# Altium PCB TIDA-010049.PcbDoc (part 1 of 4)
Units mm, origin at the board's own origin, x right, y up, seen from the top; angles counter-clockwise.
Board outline 75 x 60 mm, 4 copper layers (Top Layer, GND, Supply, Bottom Layer), stack 1.565 mm thick; 309 components, 186 nets, 995 pads, 362 vias.
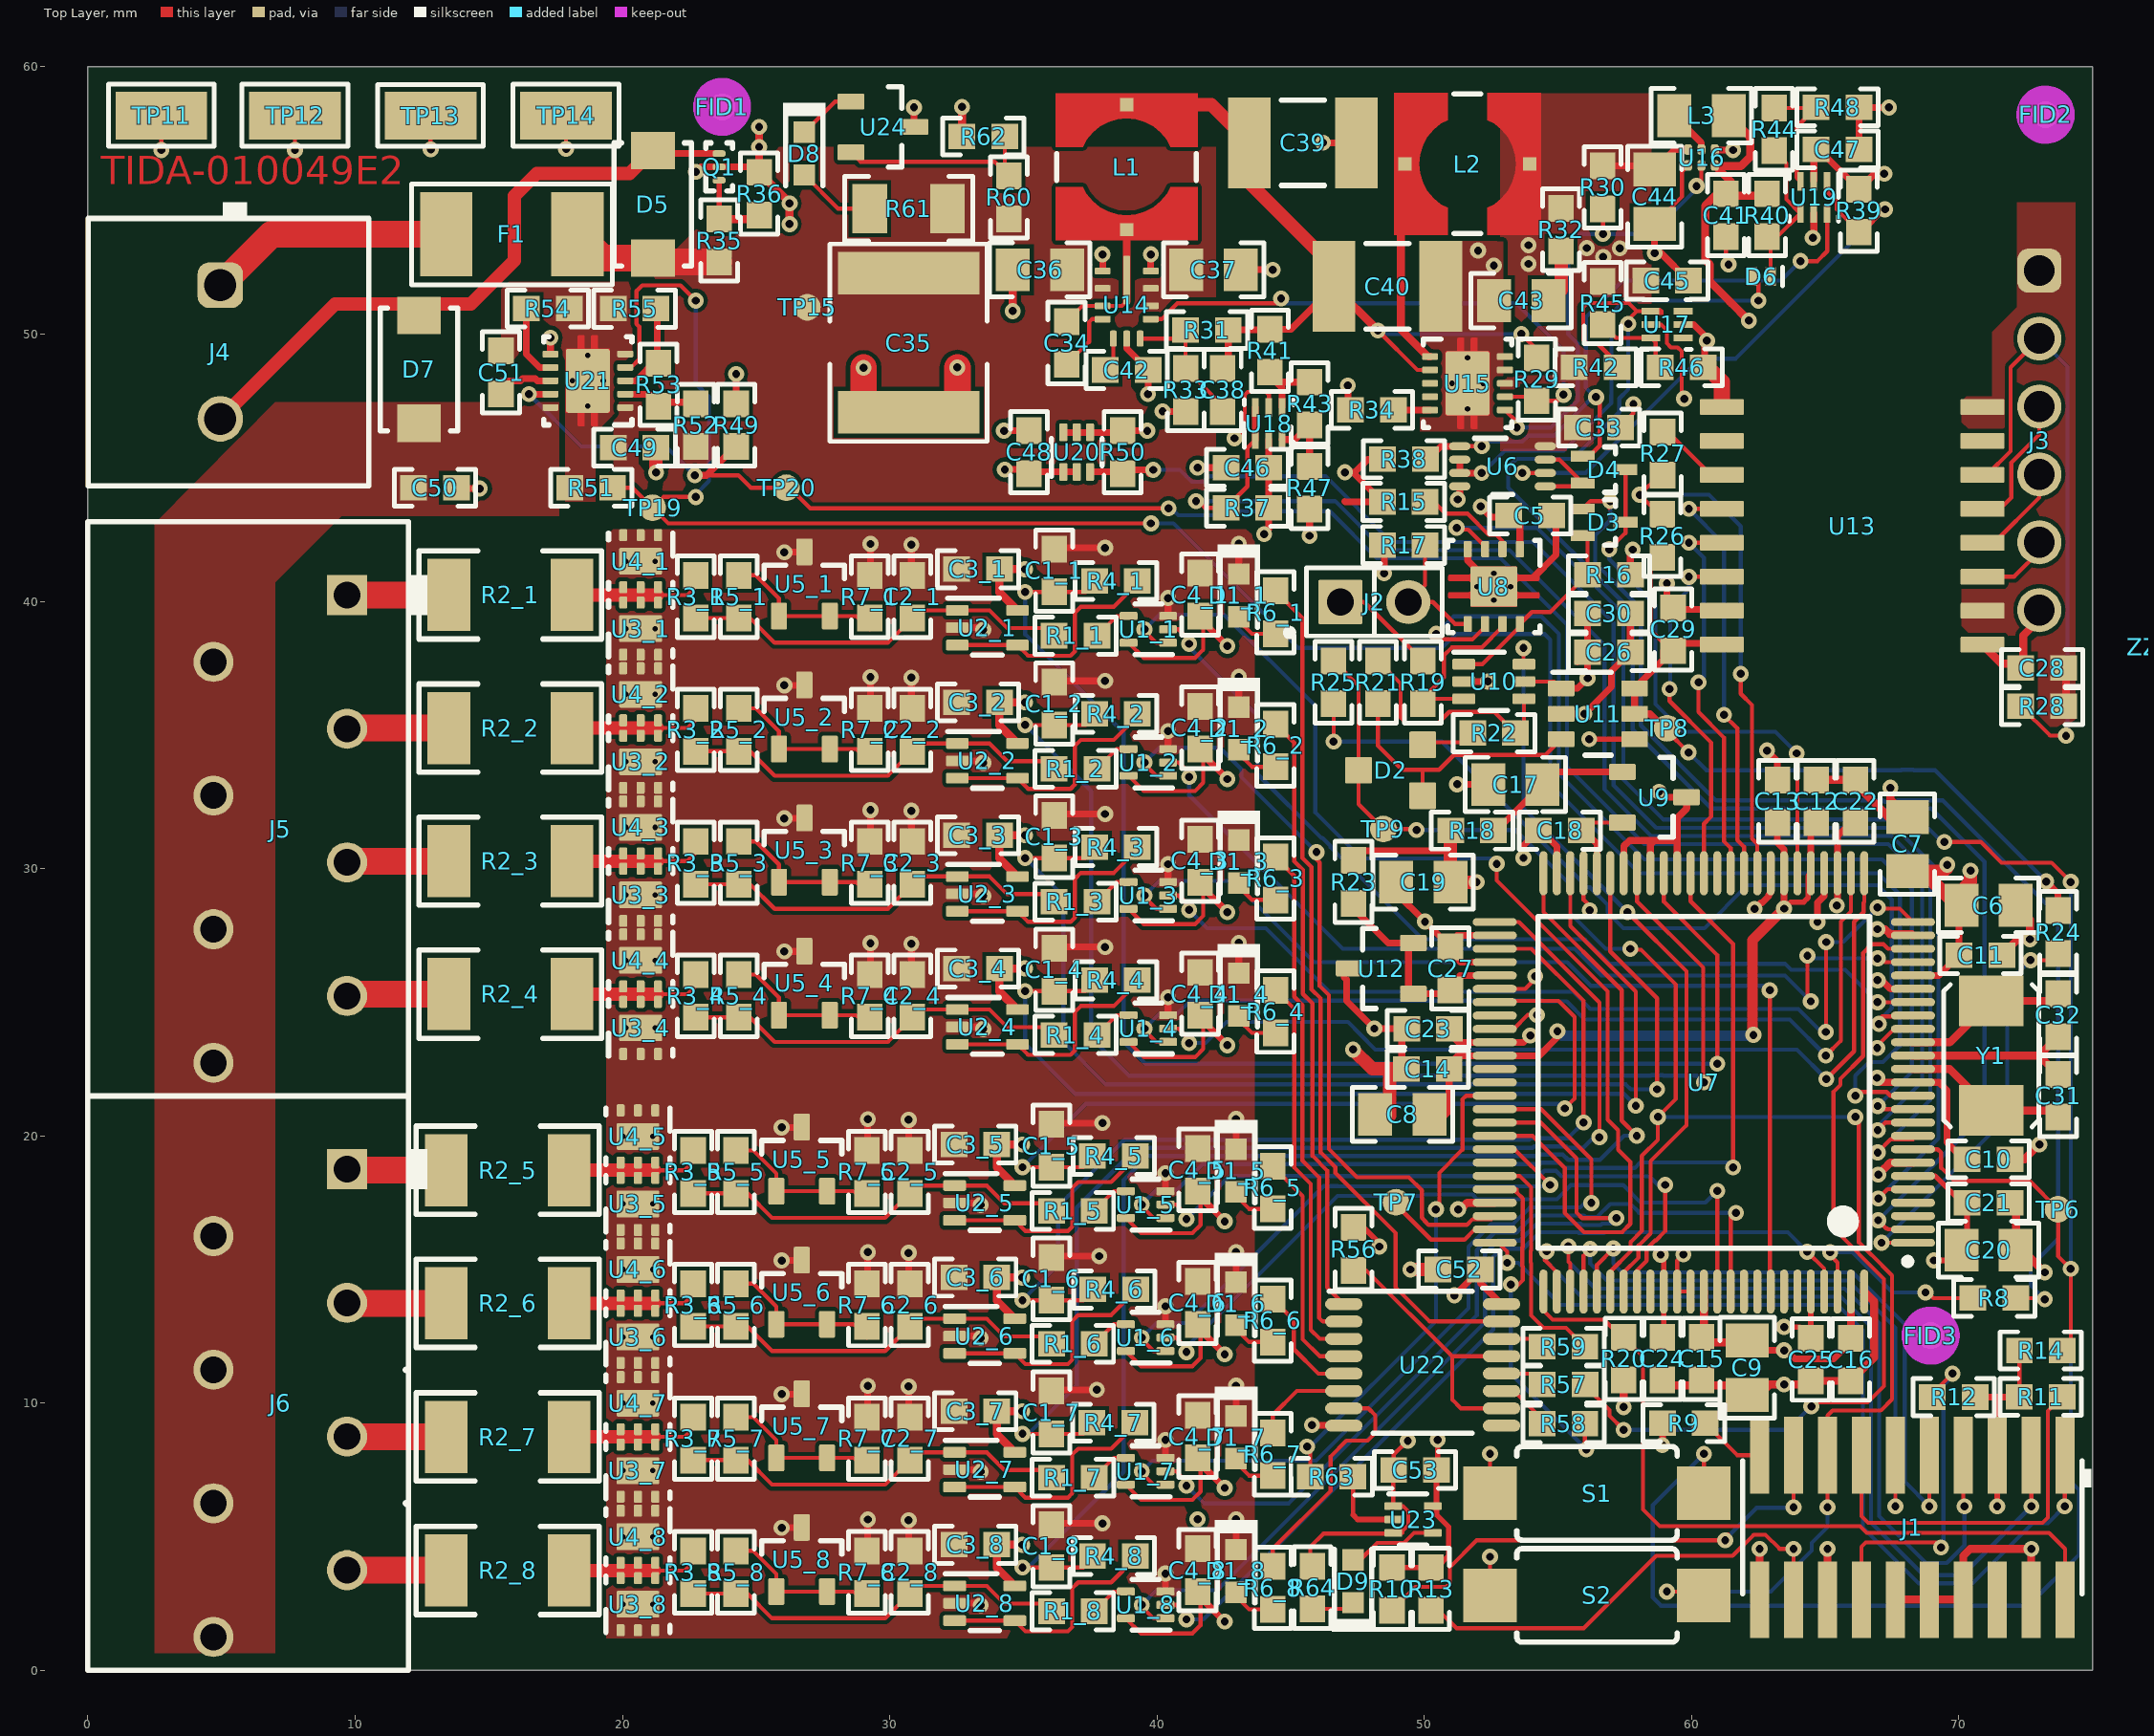
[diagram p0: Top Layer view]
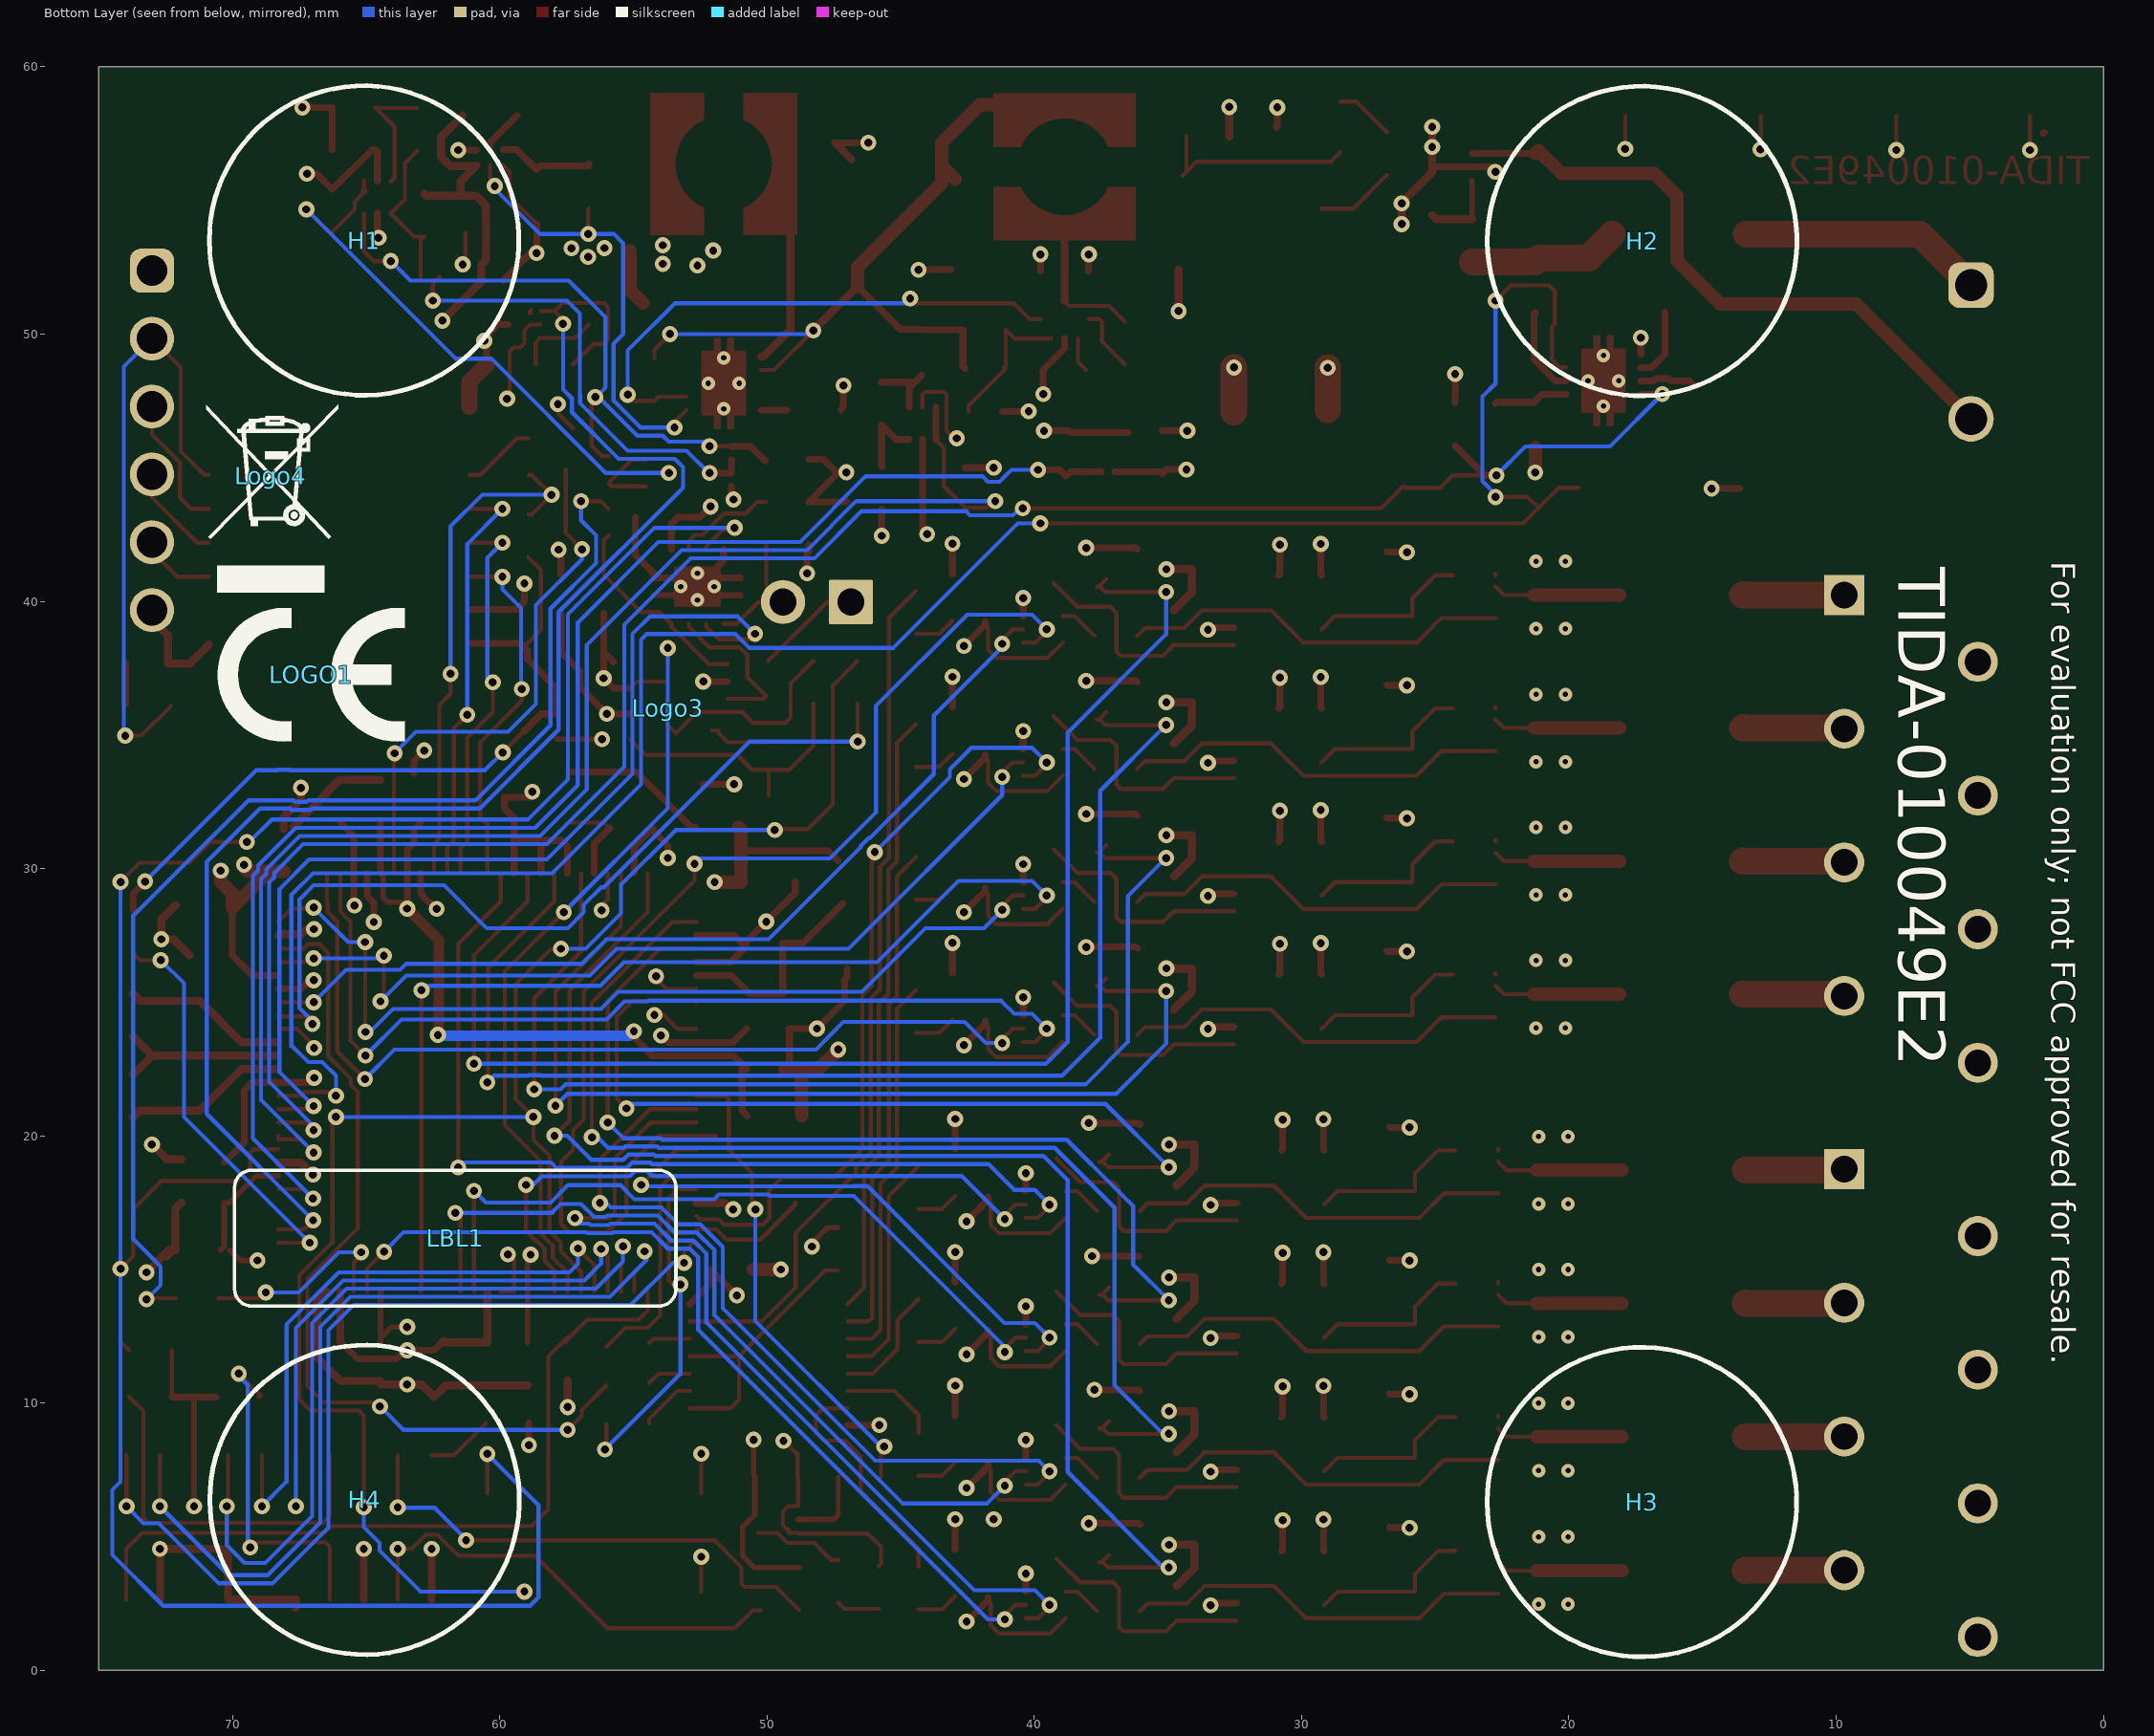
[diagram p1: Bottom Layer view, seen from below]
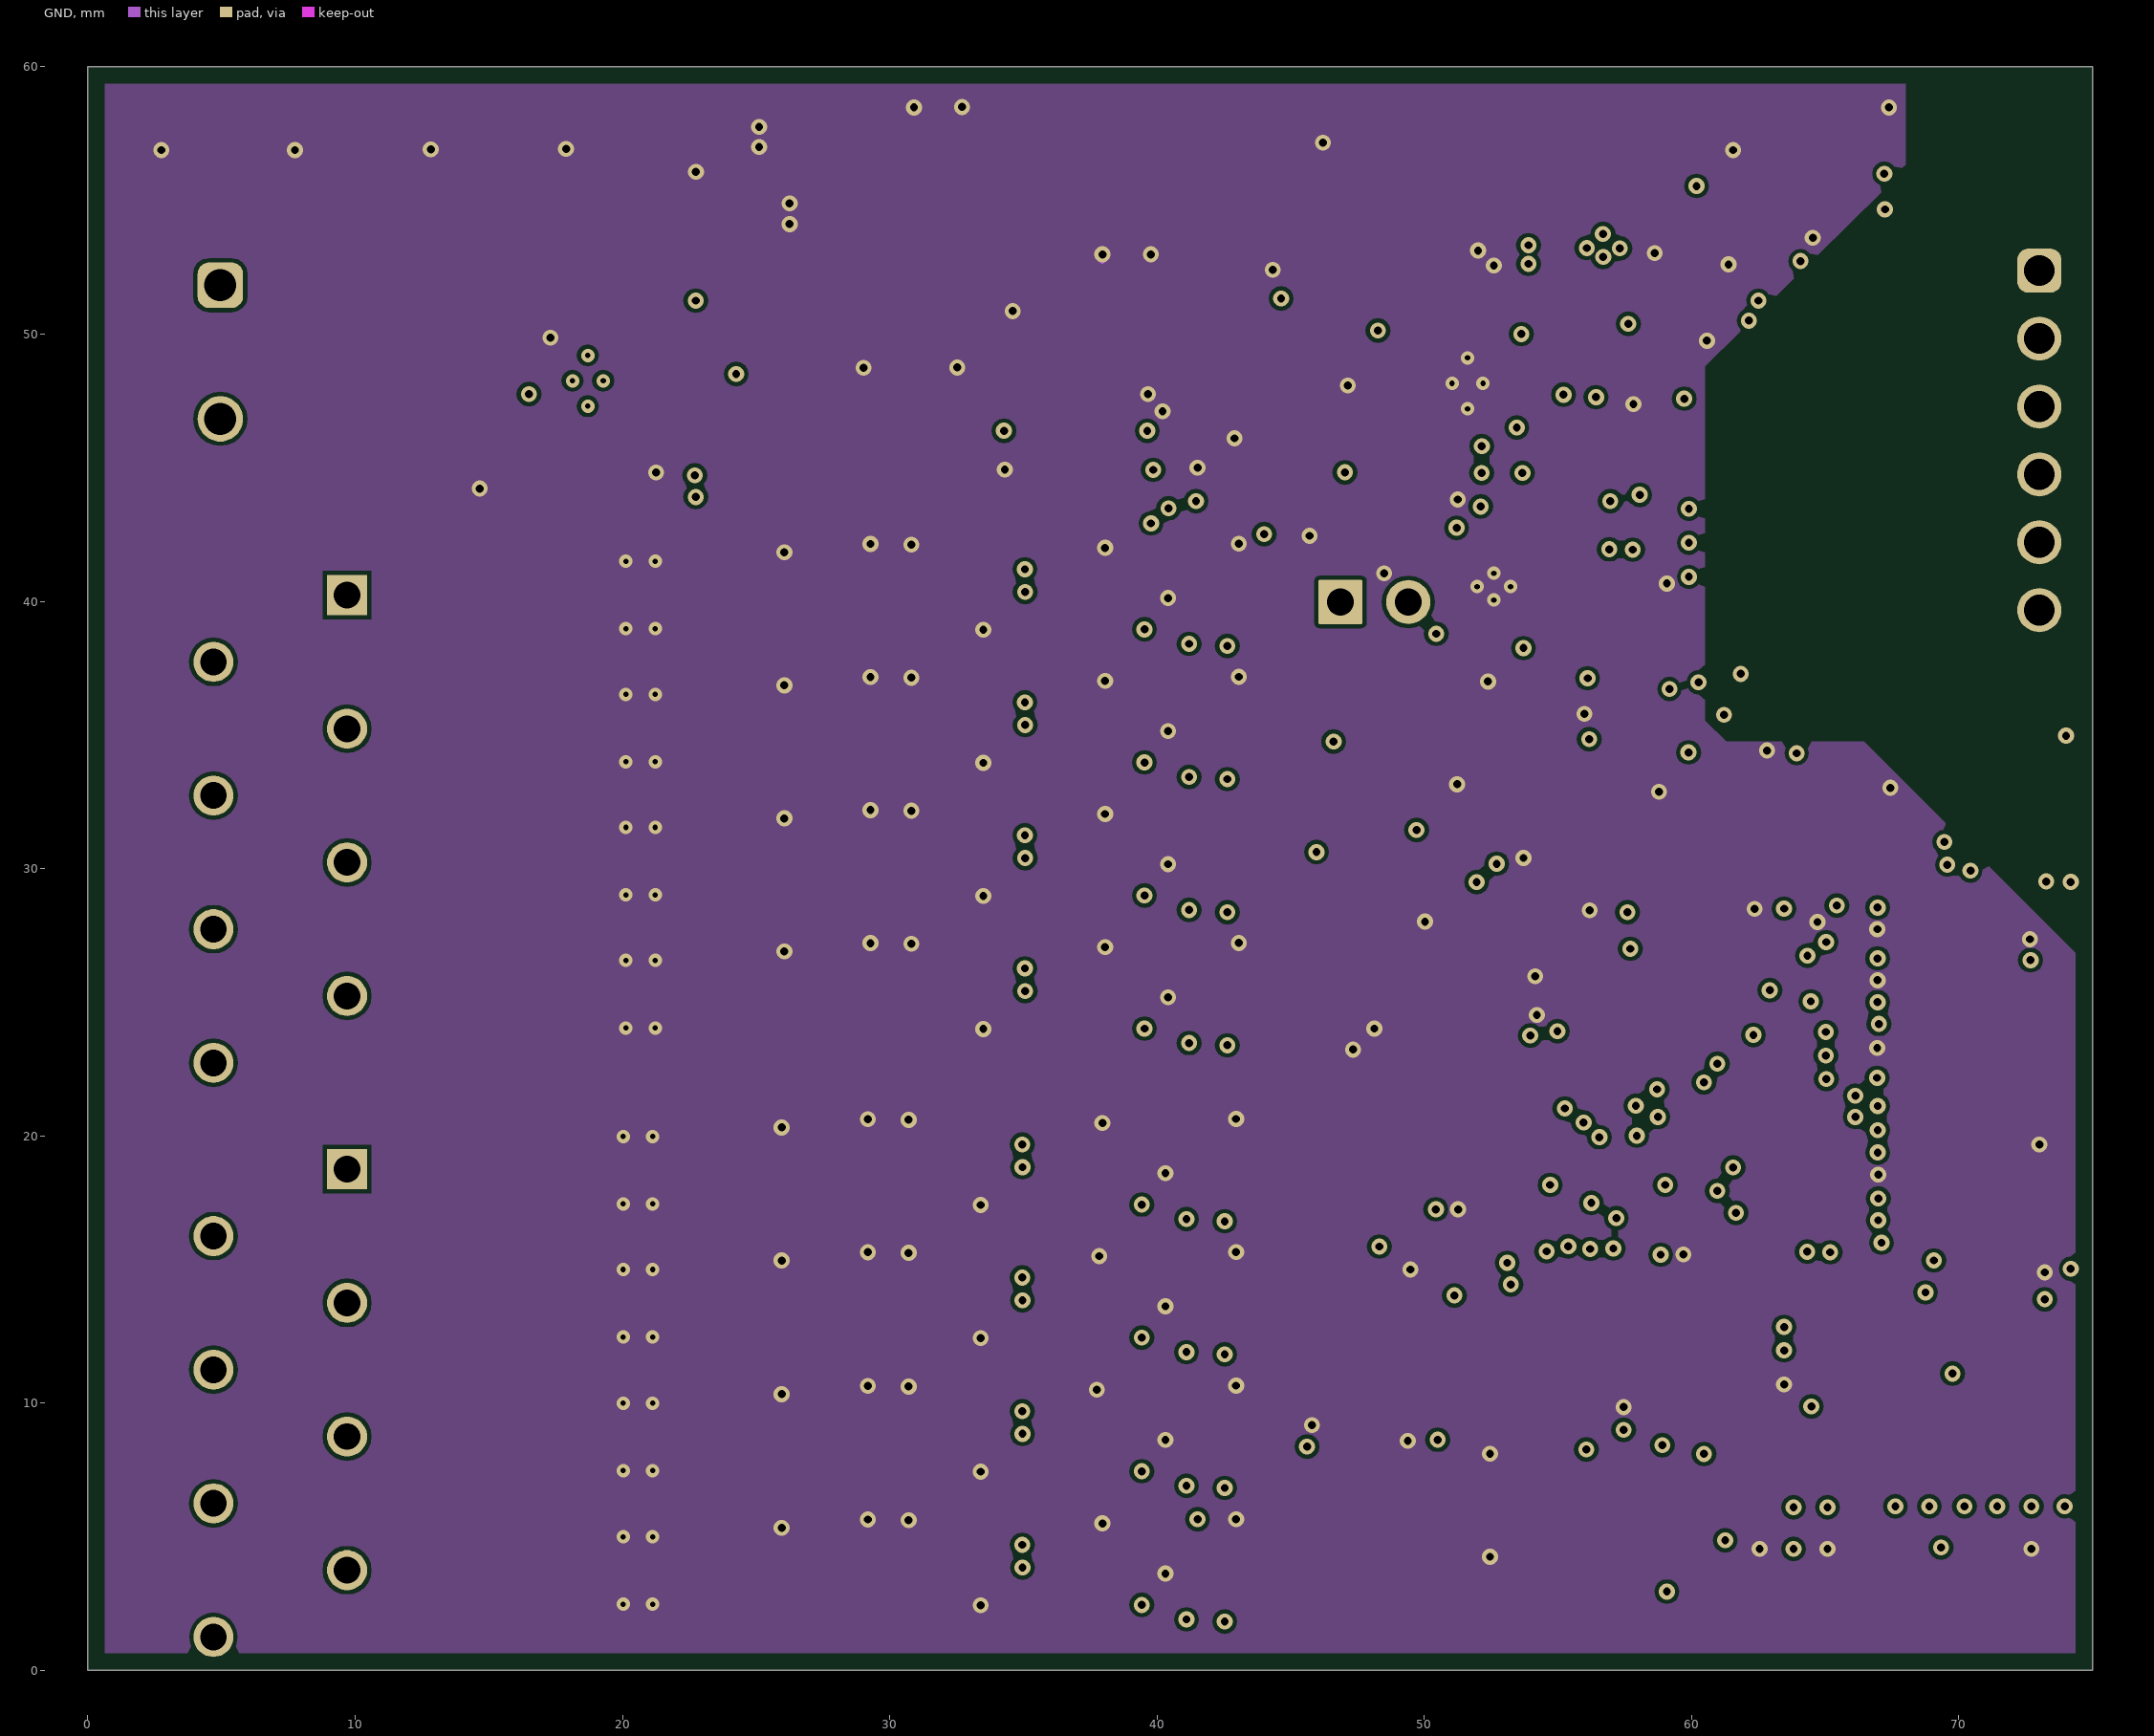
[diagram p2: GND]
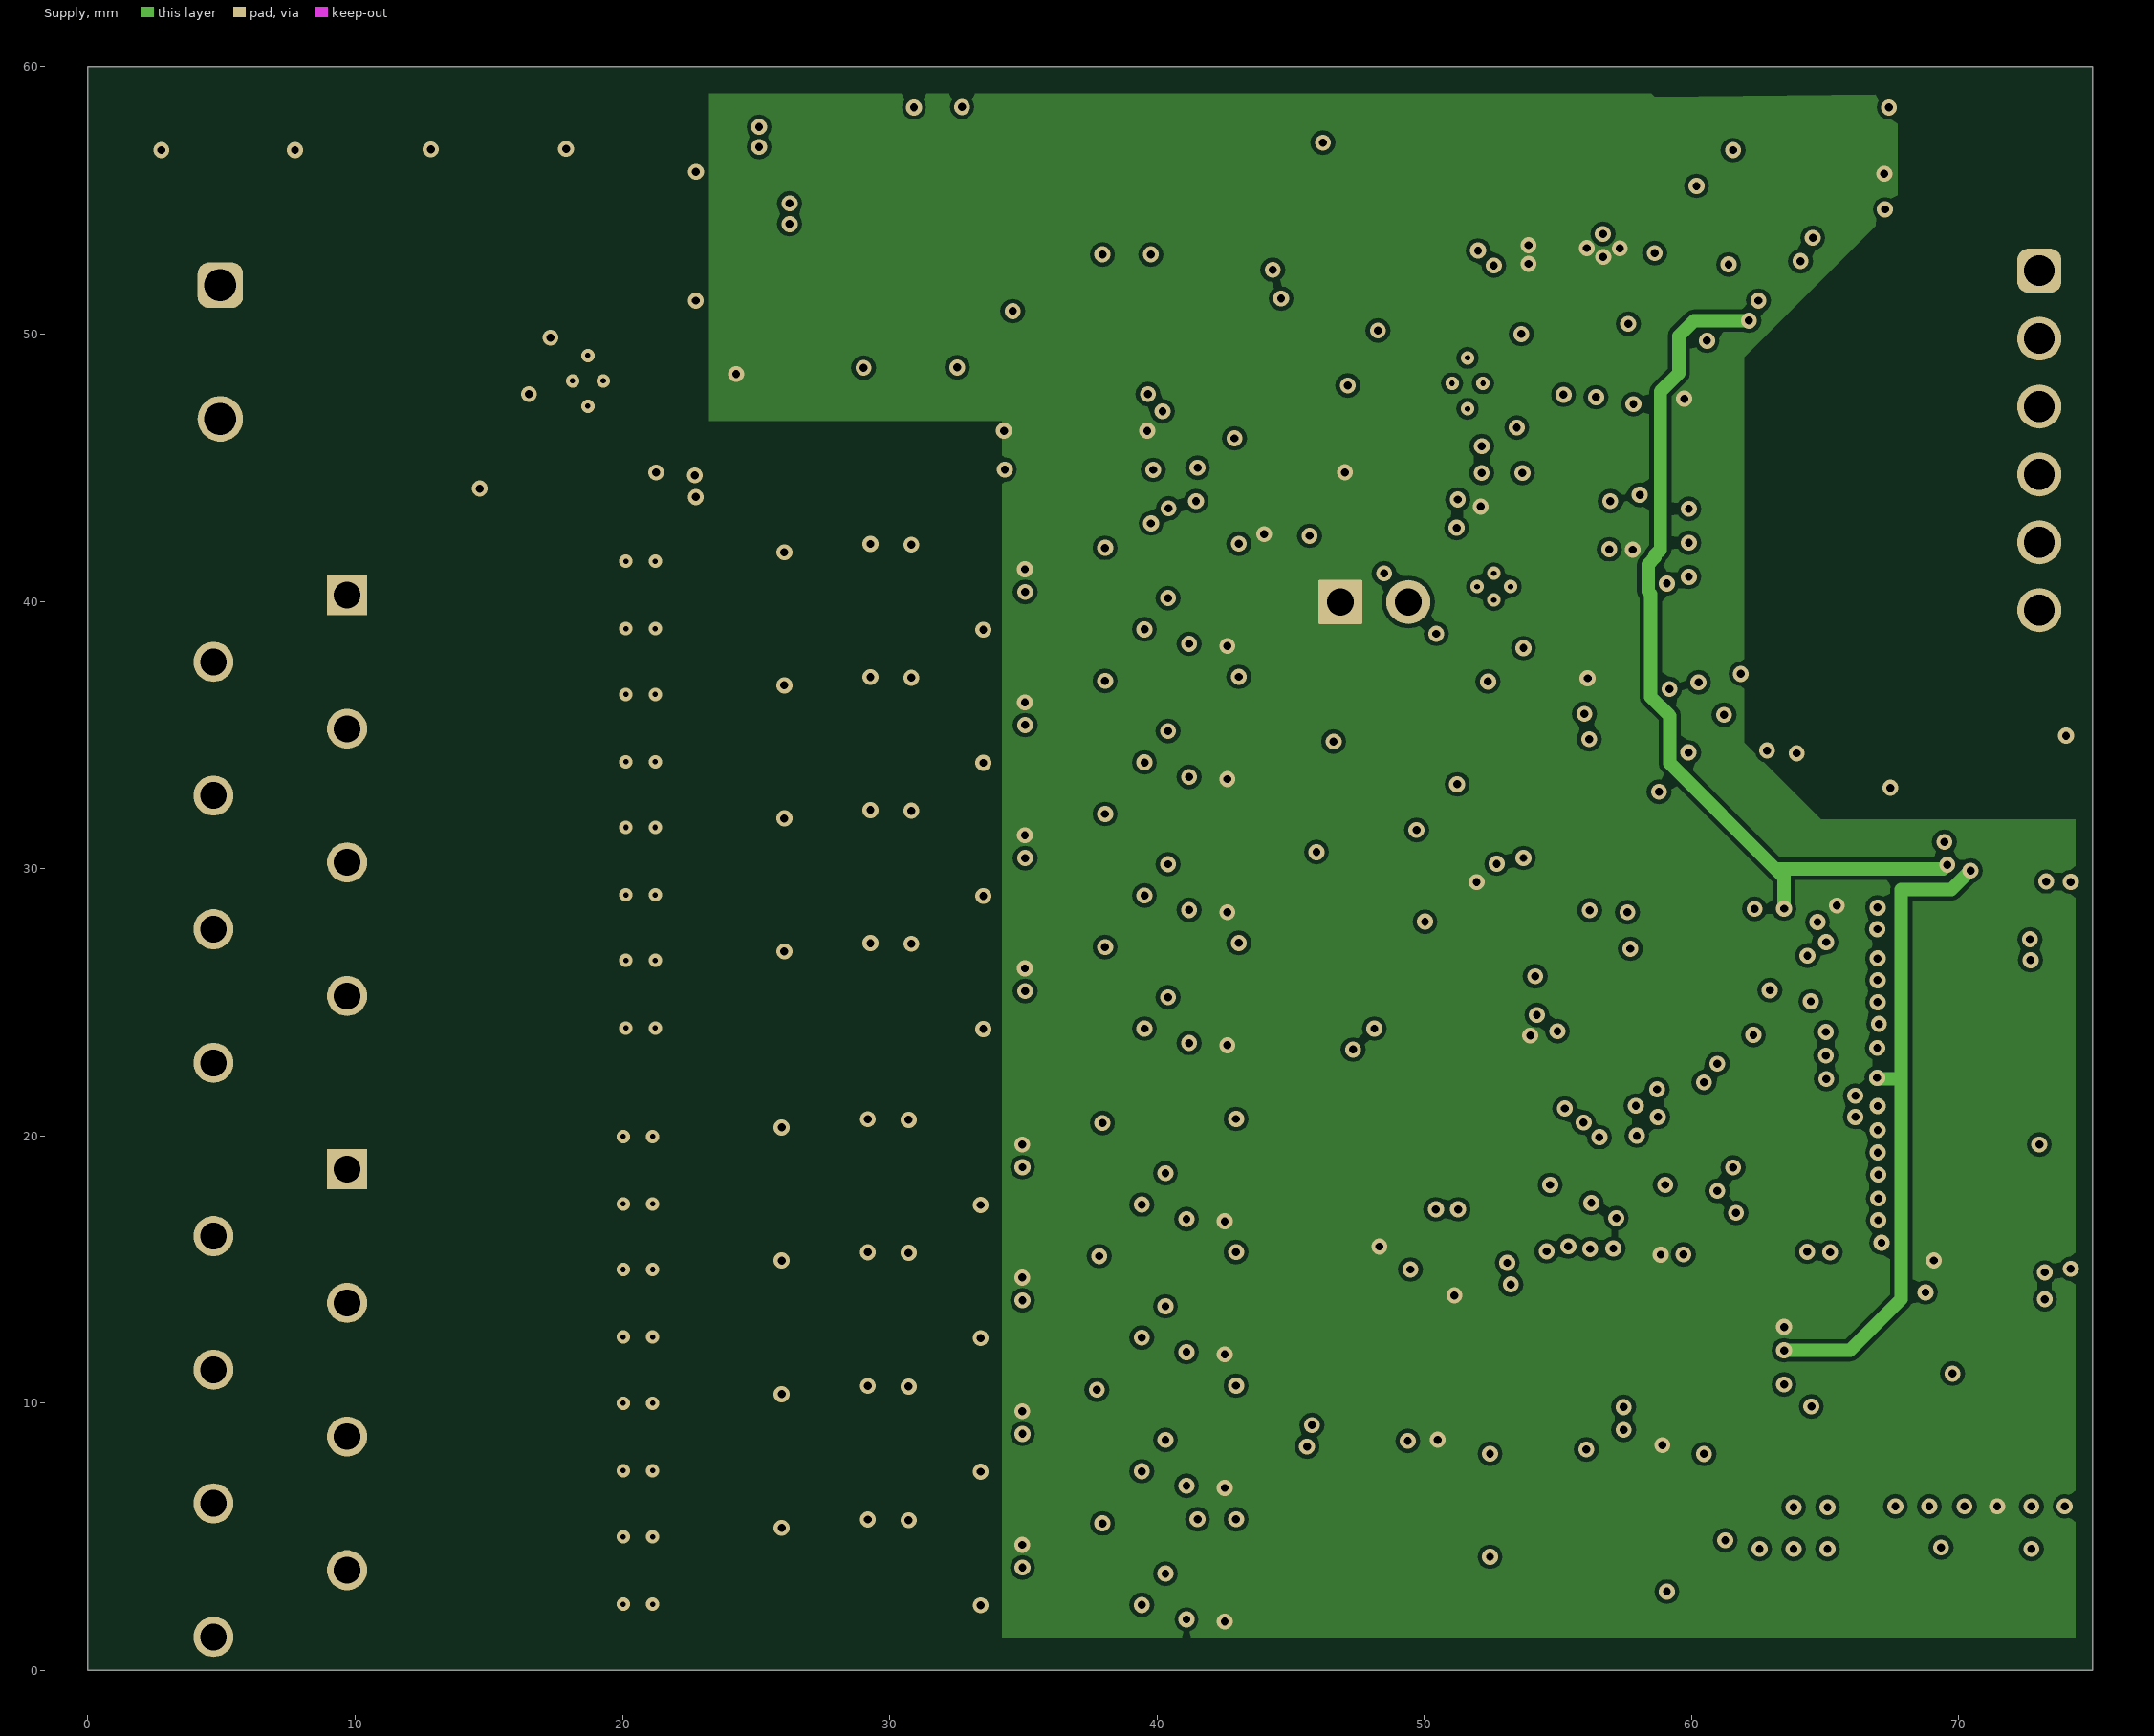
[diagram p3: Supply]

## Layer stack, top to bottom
Top Solder: solder mask 0.0102, Solder Resist, Dk 3.5
Top Layer: signal copper 0.0356
Dielectric 1: prepreg 0.2032, FR-4, Dk 4.2
GND: signal copper 0.0356
Dielectric 2: core 1.016, FR-4, Dk 4.2
Supply: signal copper 0.0356
Dielectric 3: prepreg 0.2032, FR-4, Dk 4.2
Bottom Layer: signal copper 0.0356
Bottom Solder: solder mask 0.0102, Solder Resist, Dk 3.5

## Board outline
0,0 75,0 75,60 0,60

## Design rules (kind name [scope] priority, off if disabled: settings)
AcuteAngle [All] p1: minimum=4.50000000000000E+0001 checktracksonly=FALSE
AssemblyTestPointUsage [All] p1: valid=2
BoardOutlineClearance BoardOutlineClearance_MountingHoles [OnCopper and InComponentClass('Mounting Holes')] p1: gap=1 ignorepadtopadclearanceinfootprint=FALSE
BoardOutlineClearance BoardOutlineClearance_Poly [OnCopper and IsPoly] p2: gap=0.635 ignorepadtopadclearanceinfootprint=FALSE
BoardOutlineClearance [OnCopper and Not InComponentClass('Logo') and not InComponentClass('FiducialMark') and not InRegion(1000,500,4000,800) and not InPoly] p3: gap=1.905 ignorepadtopadclearanceinfootprint=FALSE
Clearance PowerPlaneRule [InNamedPolygon('TOP_LAYER_24V_P000')] p1: gap=0.152 ignorepadtopadclearanceinfootprint=FALSE
Clearance Clearance_Keepouts [((IsTrack Or IsArc) And Not InPoly) And IsFree and IsKeepOut vs ((IsTrack Or IsArc) And Not InPoly) And IsFree and IsKeepOut] p2: gap=0 ignorepadtopadclearanceinfootprint=FALSE
Clearance Clearance_Poly [InPolygon] p3: gap=0.152 ignorepadtopadclearanceinfootprint=TRUE
Clearance Clearance_FiducialMark [IsKeepOut and InComponentClass('FiducialMark') vs IsPad and InComponentClass('FiducialMark')] p4: gap=0 ignorepadtopadclearanceinfootprint=FALSE
Clearance [All] p5: gap=0.15 ignorepadtopadclearanceinfootprint=TRUE
ComponentClearance ComponentClearance_MountingHoles_FiducialMarks [InComponentClass('Mounting Holes') vs InComponentClass('FiducialMark')] p1: gap=1.27 collisioncheckmode=3 verticalgap=0.254 showdistances=FALSE
ComponentClearance ComponentClearance_Shunt [InComponentClass('Header') vs InComponentClass('Shunt')] p2: gap=0 collisioncheckmode=3 verticalgap=0 showdistances=FALSE
ComponentClearance ComponentClearance_Logo [InComponentClass('Logo')] p3: gap=1.27 collisioncheckmode=3 verticalgap=0.254 showdistances=FALSE
ComponentClearance ComponentClearance_ScrewToNut [(HasFootprint('NY PMS 440 0025 PH')) vs (HasFootprint('Keystone_1902C'))] p4: gap=0.127 collisioncheckmode=3 verticalgap=0.254 showdistances=FALSE
ComponentClearance ComponentClearance_MountingHoles [InComponentClass('Mounting Holes')] p5: gap=6.35 collisioncheckmode=3 verticalgap=2540 showdistances=FALSE
ComponentClearance ComponentClearance_SmallPassives [HasFootprint('0201*') or HasFootprint('0402*') or HasFootprint('0508') or HasFootprint('0603*') or HasFootprint('0612') or HasFootprint('0805*') or HasFootprint('0815*') or HasFootprint('0830*') or HasFootprint('1206*') or HasFootprint('1210*') or HasFootprint('1808*') or HasFootprint('1812*') or HasFootprint('1825*') or HasFootprint('2010*') or HasFootprint('2220*') or HasFootprint('2225*') or HasFootprint('2512*') or HasFootprint('2728*') or HasFootprint('3518*') vs HasFootprint('0201*') or HasFootprint('0402*') or HasFootprint('0508') or HasFootprint('0603*') or HasFootprint('0612') or HasFootprint('0805*') or HasFootprint('0815*') or HasFootprint('0830*') or HasFootprint('1206*') or HasFootprint('1210*') or HasFootprint('1808*') or HasFootprint('1812*') or HasFootprint('1825*') or HasFootprint('2010*') or HasFootprint('2220*') or HasFootprint('2225*') or HasFootprint('2512*') or HasFootprint('2728*') or HasFootprint('3518*')] p6: gap=0.38 collisioncheckmode=3 verticalgap=0.254 showdistances=FALSE
ComponentClearance ComponentClearance_THtoSMT [IsThruComponent vs IsSMTComponent] p7: gap=1.016 collisioncheckmode=3 verticalgap=0.762 showdistances=FALSE
ComponentClearance ComponentClearance_THtoTH [IsThruComponent vs IsThruComponent] p8: gap=0.762 collisioncheckmode=3 verticalgap=0.762 showdistances=FALSE
ComponentClearance [All] p9: gap=0.762 collisioncheckmode=3 verticalgap=0.254 showdistances=FALSE
DiffPairsRouting [All] p1: maxlimit=2.54 minlimit=0.254 mostfreqgap=0.254 toplayer_minwidth=0.381 toplayer_maxwidth=0.381 toplayer_prefwidth=0.381 midlayer1_minwidth=0.381 midlayer1_maxwidth=0.381 midlayer1_prefwidth=0.381 midlayer2_minwidth=0.381 midlayer2_maxwidth=0.381 midlayer2_prefwidth=0.381 bottomlayer_minwidth=0.381 bottomlayer_maxwidth=0.381 bottomlayer_prefwidth=0.381 maxuncoupledlength=25.4
FabricationTestPointUsage TestPointUsage [All] p1: valid=2 allowmultiple=FALSE
FabricationTestpoint Testpoint [All] p1: side=3 testpointundercomponent=TRUE minsize=1.016 maxsize=2.54 preferedsize=1.524 minholesize=0 maxholesize=1.016 preferedholesize=0.813 testpointgrid=0.025 allowsidetop=TRUE allowsidebottom=TRUE usegrid=TRUE gridtolerance=0
FanoutControl Fanout_LCC [IsLCC] p1: bgadir=Out bgaviamode=Centered fanoutstyle=Auto fanoutdirection=Alternating viagrid=0.025 // Fanout_LCC (Default Rule)
FanoutControl Fanout_BGA [IsBGA] p2: bgadir=Out bgaviamode=Centered fanoutstyle=Auto fanoutdirection=Alternating viagrid=0.025 // Fanout_BGA (Default Rule)
FanoutControl Fanout_Default [All] p4: bgadir=Out bgaviamode=Centered fanoutstyle=Auto fanoutdirection=Alternating viagrid=0.025 // Fanout_Default (Default Rule)
FanoutControl Fanout_Small [(CompPinCount < 5)] p5: bgadir=Out bgaviamode=Centered fanoutstyle=Auto fanoutdirection=OutThenIn viagrid=0.025 // Fanout_Small (Default Rule)
HoleSize [All] p1: absolutevalues=TRUE maxlimit=6.375 minlimit=0.3 maxpercent=80.000 minpercent=20.000
MinimumAnnularRing MinimumAnnularRing_ThermalPadVias [IsVia and InAnyComponent] p1: minimumring=0.15
MinimumAnnularRing [All] p2: minimumring=0.15
MinimumSolderMaskSliver MinimumSolderMaskSliver_Logo [InComponentClass('Logo') vs InComponentClass('Logo')] p1: minsoldermaskwidth=0.018
MinimumSolderMaskSliver [All] p2: minsoldermaskwidth=0.1
PlaneClearance [All] p1: clearance=0.2
PlaneConnect [All] p1: planeconnectstyle=Direct reliefexpansion=0.254 reliefentries=4 reliefconductorwidth=0.254 reliefairgap=0.254
PolygonConnect [All] p1: connectstyle=Direct reliefconductorwidth=0.254 reliefentries=4 polygonreliefangle="90 Angle" airgapwidth=0.254
RoomDefinition DI1 [InComponentClass('DI1')] p1: confinementstyle=ConfineIn formatcopy=TRUE lockcomponents=FALSE outline 12.008,37.75 45.808,37.75 45.808,42.728 12.008,42.728
RoomDefinition DI2 [InComponentClass('DI2')] p2: confinementstyle=ConfineIn formatcopy=TRUE lockcomponents=FALSE outline 12.008,32.771 45.808,32.771 45.808,37.75 12.008,37.75
RoomDefinition DI3 [InComponentClass('DI3')] p3: confinementstyle=ConfineIn formatcopy=TRUE lockcomponents=FALSE outline 12.008,27.793 45.808,27.793 45.808,32.771 12.008,32.771
RoomDefinition DI4 [InComponentClass('DI4')] p4: confinementstyle=ConfineIn formatcopy=TRUE lockcomponents=FALSE outline 12.008,22.814 45.808,22.814 45.808,27.793 12.008,27.793
RoomDefinition DI5 [InComponentClass('DI5')] p5: confinementstyle=ConfineIn formatcopy=TRUE lockcomponents=FALSE outline 11.908,16.228 45.708,16.228 45.708,21.207 11.908,21.207
RoomDefinition DI6 [InComponentClass('DI6')] p6: confinementstyle=ConfineIn formatcopy=TRUE lockcomponents=FALSE outline 11.908,11.25 45.708,11.25 45.708,16.228 11.908,16.228
RoomDefinition DI7 [InComponentClass('DI7')] p7: confinementstyle=ConfineIn formatcopy=TRUE lockcomponents=FALSE outline 11.908,6.25 45.708,6.25 45.708,11.229 11.908,11.229
RoomDefinition DI8 [InComponentClass('DI8')] p8: confinementstyle=ConfineIn formatcopy=TRUE lockcomponents=FALSE outline 11.908,1.25 45.708,1.25 45.708,6.229 11.908,6.229
RoutingVias ThermalPadVias [IsVia and InAnyComponent] p1: holewidth=0.2 width=0.5 viastyle="Through Hole" minholewidth=0.2 minwidth=0.5 maxholewidth=0.33 maxwidth=0.6
RoutingVias [All] p2: holewidth=0.406 width=0.864 viastyle="Through Hole" minholewidth=0.3 minwidth=0.6 maxholewidth=1.016 maxwidth=1.651
SilkToBoardRegionClearance [Not ((IsComment or IsDesignator) And (Hide <> 'False')) and not InRegion(1000,500,4000,800)] p1:
SilkToSilkClearance SilkToSilkClearance_Pb-FreeLogo [(HasFootprint('Pb-Free_Overlay_Medium') OR HasFootprint('Pb-Free_Overlay_Small')) vs (HasFootprint('Pb-Free_Overlay_Medium') OR HasFootprint('Pb-Free_Overlay_Small'))] p1: silktosilkclearance=0
SilkToSilkClearance [All] p2: silktosilkclearance=0.1
SilkToSolderMaskClearance SilkToComponentPadClearance [(IsPad or IsFill or IsRegion) and InAnycomponent] p1: minsilkscreentomaskgap=0.127 clearancetoexposedcopper=TRUE
SilkToSolderMaskClearance "Silk to Solder Mask Opening" [All] p2: minsilkscreentomaskgap=0.1 clearancetoexposedcopper=FALSE
SolderMaskExpansion [All] p1: expansion=0.05
UnRoutedNet [All] p1: checkbadconnections=TRUE
Width [All] p1: maxlimit=2.54 minlimit=0.152 preferedwidth=0.254 checkconnectedcopper=TRUE
13 further rules are at their usual default settings.

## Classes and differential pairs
channel class TIDA-010049_DigitalInputChan: DI1 DI2 DI3 DI4 DI5 DI6 DI7 DI8
component class U_TIDA-010049_Hardware: !PCB1 FID1 FID2 FID3 H1 H2 H3 H4 LBL1 LOGO1 Logo3 Logo4 ZZ1 ZZ2 ZZ3 ZZ4
component class Label: LBL1
component class FiducialMark: FID1 FID2 FID3
component class AssemblyNote: ZZ1 ZZ2 ZZ3 ZZ4
polygon class PolygonClass_1: TOP_LAYER_24V_P000
net class DI_LED[1..8]: DI_LED1 DI_LED2 DI_LED3 DI_LED4 DI_LED5 DI_LED6 DI_LED7 DI_LED8
component class U_TIDACBL-0053_LED: C52 C53 D8 D9 R56 R57 R58 R59 R60 R61 R62 R63 R64 R84 R85 R86 U22 U23 U24 U27
component class DI8: C1_8 C2_8 C3_8 C4_8 D1_8 R1_8 R2_8 R3_8 R4_8 R5_8 R6_8 R7_8 U1_8 U2_8 U3_8 U4_8 U5_8
component class DI7: C1_7 C2_7 C3_7 C4_7 D1_7 R1_7 R2_7 R3_7 R4_7 R5_7 R6_7 R7_7 U1_7 U2_7 U3_7 U4_7 U5_7
component class DI6: C1_6 C2_6 C3_6 C4_6 D1_6 R1_6 R2_6 R3_6 R4_6 R5_6 R6_6 R7_6 U1_6 U2_6 U3_6 U4_6 U5_6
component class DI5: C1_5 C2_5 C3_5 C4_5 D1_5 R1_5 R2_5 R3_5 R4_5 R5_5 R6_5 R7_5 U1_5 U2_5 U3_5 U4_5 U5_5
component class DI4: C1_4 C2_4 C3_4 C4_4 D1_4 R1_4 R2_4 R3_4 R4_4 R5_4 R6_4 R7_4 U1_4 U2_4 U3_4 U4_4 U5_4
component class DI3: C1_3 C2_3 C3_3 C4_3 D1_3 R1_3 R2_3 R3_3 R4_3 R5_3 R6_3 R7_3 U1_3 U2_3 U3_3 U4_3 U5_3
component class DI2: C1_2 C2_2 C3_2 C4_2 D1_2 R1_2 R2_2 R3_2 R4_2 R5_2 R6_2 R7_2 U1_2 U2_2 U3_2 U4_2 U5_2
component class DI1: C1_1 C2_1 C3_1 C4_1 D1_1 R1_1 R2_1 R3_1 R4_1 R5_1 R6_1 R7_1 U1_1 U2_1 U3_1 U4_1 U5_1
net class DI_FAIL[1..8]: DI_FAIL1 DI_FAIL2 DI_FAIL3 DI_FAIL4 DI_FAIL5 DI_FAIL6 DI_FAIL7 DI_FAIL8
component class TIDA-010049_Top: J3 J4 J5 J6 J?
component class Header: J1 J2 J3
net class DI_LOGIC[1..8]: DI_LOGIC1 DI_LOGIC2 DI_LOGIC3 DI_LOGIC4 DI_LOGIC5 DI_LOGIC6 DI_LOGIC7 DI_LOGIC8
net class DIAG_CTRL[1..8]: DIAG_CTRL0 DIAG_CTRL1 DIAG_CTRL2 DIAG_CTRL3 DIAG_CTRL4 DIAG_CTRL5 DIAG_CTRL6 DIAG_CTRL7 DIAG_CTRL8
net class DI_IN[1..8]: DI_IN1 DI_IN2 DI_IN3 DI_IN4 DI_IN5 DI_IN6 DI_IN7 DI_IN8
component class U_TIDACBL-0053_Power: C34 C35 C36 C37 C38 C39 C40 C41 C42 C43 C44 C45 C46 C47 C48 C49 C50 C51 D5 D6 D7 F1 L1 L2 L3 Q1 R7 R29 R30 R31 R32 R33 R34 R35 R36 R37 R38 R39 R40 R41 R42 R43 R44 R45 R46 R47 R48 R49 R50 R51 R52 R53 R54 R55 R? TP15 TP19 TP20 TP21 TP? U14 U15 U16 U17 U18 U19 U20 U21
component class U_TIDACBL-0053_Hercules: C3 C4 C5 C6 C7 C8 C9 C10 C11 C12 C13 C14 C15 C16 C17 C18 C19 C20 C21 C22 C23 C24 C25 C26 C27 C28 C29 C30 C31 C32 C33 D2 D3 D4 J1 J2 R8 R9 R10 R11 R12 R13 R14 R15 R16 R17 R18 R19 R20 R21 R22 R23 R24 R25 R26 R27 R28 S1 S2 TP1 TP5 TP6 TP7 TP8 TP9 TP11 TP12 TP13 TP14 U6 U7 U8 U9 U10 U11 U12 U13 Y1

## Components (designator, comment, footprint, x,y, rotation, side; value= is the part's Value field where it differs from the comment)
C1_1 "GRM188R71A564KA61D" 0603 36.152,41.15 r90 top value=0.56uF (schematic designator C1)
C1_2 "GRM188R71A564KA61D" 0603 36.152,36.171 r90 top value=0.56uF (schematic designator C1)
C1_3 "GRM188R71A564KA61D" 0603 36.152,31.193 r90 top value=0.56uF (schematic designator C1)
C1_4 "GRM188R71A564KA61D" 0603 36.152,26.214 r90 top value=0.56uF (schematic designator C1)
C1_5 "GRM188R71A564KA61D" 0603 36.052,19.628 r90 top value=0.56uF (schematic designator C1)
C1_6 "GRM188R71A564KA61D" 0603 36.052,14.65 r90 top value=0.56uF (schematic designator C1)
C1_7 "GRM188R71A564KA61D" 0603 36.052,9.65 r90 top value=0.56uF (schematic designator C1)
C1_8 "GRM188R71A564KA61D" 0603 36.052,4.65 r90 top value=0.56uF (schematic designator C1)
C2_1 "0603ZC101KAT2A" 0603 30.85,40.171 r90 top value=100pF (schematic designator C2)
C2_2 "0603ZC101KAT2A" 0603 30.85,35.192 r90 top value=100pF (schematic designator C2)
C2_3 "0603ZC101KAT2A" 0603 30.85,30.214 r90 top value=100pF (schematic designator C2)
C2_4 "0603ZC101KAT2A" 0603 30.85,25.235 r90 top value=100pF (schematic designator C2)
C2_5 "0603ZC101KAT2A" 0603 30.75,18.649 r90 top value=100pF (schematic designator C2)
C2_6 "0603ZC101KAT2A" 0603 30.75,13.671 r90 top value=100pF (schematic designator C2)
C2_7 "0603ZC101KAT2A" 0603 30.75,8.671 r90 top value=100pF (schematic designator C2)
C2_8 "0603ZC101KAT2A" 0603 30.75,3.671 r90 top value=100pF (schematic designator C2)
C3_1 "GRM188R71C104KA01D" 0603 33.304,41.2 r180 top value=0.1uF (schematic designator C3)
C3_2 "GRM188R71C104KA01D" 0603 33.304,36.221 r180 top value=0.1uF (schematic designator C3)
C3_3 "GRM188R71C104KA01D" 0603 33.304,31.243 r180 top value=0.1uF (schematic designator C3)
C3_4 "GRM188R71C104KA01D" 0603 33.304,26.264 r180 top value=0.1uF (schematic designator C3)
C3_5 "GRM188R71C104KA01D" 0603 33.203,19.678 r180 top value=0.1uF (schematic designator C3)
C3_6 "GRM188R71C104KA01D" 0603 33.203,14.7 r180 top value=0.1uF (schematic designator C3)
C3_7 "GRM188R71C104KA01D" 0603 33.203,9.7 r180 top value=0.1uF (schematic designator C3)
C3_8 "GRM188R71C104KA01D" 0603 33.203,4.7 r180 top value=0.1uF (schematic designator C3)
C4_1 "GRM188R71C104KA01D" 0603 41.617,40.25 r90 top value=0.1uF (schematic designator C4)
C4_2 "GRM188R71C104KA01D" 0603 41.617,35.271 r90 top value=0.1uF (schematic designator C4)
C4_3 "GRM188R71C104KA01D" 0603 41.617,30.293 r90 top value=0.1uF (schematic designator C4)
C4_4 "GRM188R71C104KA01D" 0603 41.617,25.314 r90 top value=0.1uF (schematic designator C4)
C4_5 "GRM188R71C104KA01D" 0603 41.516,18.728 r90 top value=0.1uF (schematic designator C4)
C4_6 "GRM188R71C104KA01D" 0603 41.516,13.75 r90 top value=0.1uF (schematic designator C4)
C4_7 "GRM188R71C104KA01D" 0603 41.516,8.75 r90 top value=0.1uF (schematic designator C4)
C4_8 "GRM188R71C104KA01D" 0603 41.516,3.75 r90 top value=0.1uF (schematic designator C4)
C5 "GRM188R71C104KA01D" 0603 53.958,43.21 r0 top value=0.1uF
C6 "JMK212B7106KG-T" 0805_HV 71.108,28.625 r0 top value=10uF
C7 "JMK212B7106KG-T" 0805_HV 68.075,30.918 r90 top value=10uF
C8 "JMK212B7106KG-T" 0805_HV 49.179,20.805 r180 top value=10uF
C9 "JMK212B7106KG-T" 0805_HV 62.083,11.325 r270 top value=10uF
C10 "GRM188R71C104KA01D" 0603 71.108,19.125 r0 top value=0.1uF
C11 "GRM188R71C104KA01D" 0603 70.808,26.764 r0 top value=0.1uF
C12 "GRM188R71C104KA01D" 0603 64.658,32.518 r90 top value=0.1uF
C13 "GRM188R71C104KA01D" 0603 63.208,32.518 r90 top value=0.1uF
C14 "GRM188R71C104KA01D" 0603 50.129,22.506 r180 top value=0.1uF
C15 "GRM188R71C104KA01D" 0603 60.366,11.661 r270 top value=0.1uF
C16 "GRM188R71C104KA01D" 0603 65.958,11.632 r270 top value=0.1uF
C17 "GRM21BZ71A226ME15L" 0805_HV 53.407,33.146 r180 top value=22uF
C18 "GRM188R71A105KA61D" 0603 55.07,31.419 r180 top value=1uF
C19 "JMK212B7106KG-T" 0805_HV 49.958,29.493 r180 top value=10uF
C20 "JMK212B7106KG-T" 0805_HV 71.108,15.725 r0 top value=10uF
C21 "GRM188R71C104KA01D" 0603 71.108,17.5 r0 top value=0.1uF
C22 "GRM188R71C104KA01D" 0603 66.124,32.518 r90 top value=0.1uF
C23 "GRM188R71C104KA01D" 0603 50.141,24 r180 top value=0.1uF
C24 "GRM188R71C104KA01D" 0603 58.908,11.661 r270 top value=0.1uF
C25 "GRM188R71C104KA01D" 0603 64.458,11.632 r270 top value=0.1uF
C26 "GRM188R71C104KA01D" 0603 56.908,38.1 r0 top value=0.1uF
C27 "GRM188R71A105KA61D" 0603 50.974,26.264 r90 top value=1uF
C28 "GRM188R71C104KA01D" 0603 73.112,37.507 r0 top value=0.1uF
C29 "GRM188R71C104KA01D" 0603 59.308,38.95 r90 top value=0.1uF
C30 "GRM188R71C104KA01D" 0603 56.908,39.548 r0 top value=0.1uF
C31 "GRM1885C1H330JA01D" 0603 73.708,21.5 r90 top value=33pF
C32 "GRM1885C1H330JA01D" 0603 73.708,24.514 r270 top value=33pF
C33 "GRM188R71C104KA01D" 0603 56.532,46.5 r0 top value=0.1uF
C34 "GRM188R71C104KA01D" 0603 36.616,49.664 r90 top value=0.1uF
C35 "C5750X7R2A475K230KA" 2220_250 30.708,49.675 r270 top value=4.7uF
C36 "GRM21AR72A224KAC5L" 0805_HV 35.616,52.405 r180 top value=0.22uF
C37 "GRM21AR72A224KAC5L" 0805_HV 42.116,52.405 r0 top value=0.22uF
C38 "GRM1885C1H220JA01D" 0603 42.457,47.907 r270 top value=22pF
C39 "C4532X7R1E226M250KC" 1812_280 45.458,57.158 r0 top value=22uF
C40 "C4532X7R1E226M250KC" 1812_280 48.616,51.782 r0 top value=22uF
C41 "CL10B475KQ8NQND" 0603 61.281,54.446 r270 top value=4.7uF
C42 "GRM188R71A105KA61D" 0603 38.866,48.655 r0 top value=1uF
C43 "GRM21BR71A106KE51L" 0805_HV 53.625,51.25 r180 top value=10uF
C44 "GRM21BR71A106KE51L" 0805_HV 58.616,55.139 r270 top value=10uF
C45 "GRM188R71C104KA01D" 0603 59.083,52 r0 top value=0.1uF
C46 "GRM188R71C104KA01D" 0603 43.383,45 r180 top value=0.1uF
C47 "GRM188R71C104KA01D" 0603 65.458,56.906 r0 top value=0.1uF
C48 "GRM188R71C104KA01D" 0603 35.208,45.58 r270 top value=0.1uF
C49 "" 0603 20.458,45.75 r0 top value=0.1uF
C50 "" 0603 12.989,44.25 r0 top value=0.1uF
C51 "" 0603 15.458,48.565 r90 top value=0.01uF
C52 "GRM188R71C104KA01D" 0603 51.308,15 r180 top value=0.1uF
C53 "GRM188R71C104KA01D" 0603 49.654,7.5 r180 top value=0.1uF
D1_1 "150060GS75000" WL-SMCW_GREEN 43.059,40.221 r270 top value=Green (schematic designator D1)
D1_2 "150060GS75000" WL-SMCW_GREEN 43.058,35.243 r270 top value=Green (schematic designator D1)
D1_3 "150060GS75000" WL-SMCW_GREEN 43.058,30.264 r270 top value=Green (schematic designator D1)
D1_4 "150060GS75000" WL-SMCW_GREEN 43.058,25.286 r270 top value=Green (schematic designator D1)
D1_5 "150060GS75000" WL-SMCW_GREEN 42.958,18.7 r270 top value=Green (schematic designator D1)
D1_6 "150060GS75000" WL-SMCW_GREEN 42.958,13.721 r270 top value=Green (schematic designator D1)
D1_7 "150060GS75000" WL-SMCW_GREEN 42.958,8.722 r270 top value=Green (schematic designator D1)
D1_8 "150060GS75000" WL-SMCW_GREEN 42.958,3.722 r270 top value=Green (schematic designator D1)
D2 "DB3X313F0L" Mini3-G3-B 48.739,33.679 r180 top value=30V
D3 "BAT54CT-7-F" SOT-523 56.726,42.957 r0 top value=30V
D4 "BAT54AT-7-F" SOT-523 56.724,44.927 r0 top value=30V
D5 "SMAJ30CA" SMA_Bi 21.139,54.85 r270 top value=30V
D6 "BAT54LP-7" X1-DFN1006-2 62.603,52.147 r180 top value=30V
D7 "SMAJ30CA" SMA_Bi 12.39,48.677 r270 top value=30V
D8 "low brightness" WL-SMCW_GREEN 26.808,56.75 r270 top value=Green
D9 "150060RS75000" WL-SMCW_RED 47.333,3.336 r90 top value=Red
F1 "045401.5MR" SloBlo452 15.866,53.742 r180 top
FID1 "Fiducial" Fiducial10-20 23.729,58.5 r0 top
FID2 "Fiducial" Fiducial10-20 73.241,58.208 r0 top
FID3 "Fiducial" Fiducial10-20 68.941,12.525 r0 top
H1 "SJ-5303 (CLEAR)" Bumpon_SJ5003Transparent 65.073,53.5 r180 bottom
H2 "SJ-5303 (CLEAR)" Bumpon_SJ5003Transparent 17.258,53.48 r180 bottom
H3 "SJ-5303 (CLEAR)" Bumpon_SJ5003Transparent 17.267,6.298 r180 bottom
H4 "SJ-5303 (CLEAR)" Bumpon_SJ5003Transparent 65.054,6.38 r180 bottom
J1 "FTR-110-51-S-D-06" Samtec_FTR-110-51-x-D-06 68.258,5.35 r270 top
J2 "HTSW-102-07-G-S" Samtec_HTSW-102-07-G-S 48.131,39.974 r0 top
J3 "61300611121" WURTH_61300611121 73.008,46.02 r270 top
J4 "1792863" Phoenix_1792863 4.958,49.325 r270 top
J5 "1990067" Phoenix_1990067 7.2,31.482 r270 top
J6 "1990067" Phoenix_1990067 7.2,10 r270 top
L1 "744043180" WE-TPC_4828 38.866,56.255 r90 top value=18uH
L2 "744043180" WE-TPC_4828 51.616,56.363 r0 top value=18uH
L3 "LQM21PN2R2MC0D" 0805_HV 60.366,58.174 r0 top value=2.2uH
LBL1 "THT-14-423-10" Label_650x200 61.66,16.173 r180 bottom
LOGO1 "CE Mark" CE_Mark_5mm 67.051,37.25 r180 bottom
Logo3 "FCC disclaimer" FCC_disclaimer 53.708,36 r180 bottom
Logo4 "WEEE logo" WEEE_Minimum 68.557,44.703 r180 bottom
Q1 "CSD18541F5" YJK0003A 23.616,56.25 r90 top value=60V
R1_1 "CRCW0603200RJNEA" 0603 36.952,38.714 r0 top value=200 (schematic designator R1)
R1_2 "CRCW0603200RJNEA" 0603 36.952,33.735 r0 top value=200 (schematic designator R1)
R1_3 "CRCW0603200RJNEA" 0603 36.952,28.757 r0 top value=200 (schematic designator R1)
R1_4 "CRCW0603200RJNEA" 0603 36.952,23.778 r0 top value=200 (schematic designator R1)
R1_5 "CRCW0603200RJNEA" 0603 36.852,17.192 r0 top value=200 (schematic designator R1)
R1_6 "CRCW0603200RJNEA" 0603 36.852,12.214 r0 top value=200 (schematic designator R1)
R1_7 "CRCW0603200RJNEA" 0603 36.852,7.214 r0 top value=200 (schematic designator R1)
R1_8 "CRCW0603200RJNEA" 0603 36.852,2.214 r0 top value=200 (schematic designator R1)
R2_1 "CRCW20104K99FKEF" 2010 15.808,40.236 r180 top value=4.99k (schematic designator R2)
R2_2 "CRCW20104K99FKEF" 2010 15.808,35.258 r180 top value=4.99k (schematic designator R2)
R2_3 "CRCW20104K99FKEF" 2010 15.808,30.279 r180 top value=4.99k (schematic designator R2)
R2_4 "CRCW20104K99FKEF" 2010 15.808,25.301 r180 top value=4.99k (schematic designator R2)
R2_5 "CRCW20104K99FKEF" 2010 15.708,18.715 r180 top value=4.99k (schematic designator R2)
R2_6 "CRCW20104K99FKEF" 2010 15.708,13.736 r180 top value=4.99k (schematic designator R2)
R2_7 "CRCW20104K99FKEF" 2010 15.708,8.736 r180 top value=4.99k (schematic designator R2)
R2_8 "CRCW20104K99FKEF" 2010 15.708,3.736 r180 top value=4.99k (schematic designator R2)
R3_1 "RC0603FR-071K13L" 0603 22.748,40.171 r90 top value=1.13k (schematic designator R3)
R3_2 "RC0603FR-071K13L" 0603 22.748,35.192 r90 top value=1.13k (schematic designator R3)
R3_3 "RC0603FR-071K13L" 0603 22.748,30.214 r90 top value=1.13k (schematic designator R3)
R3_4 "RC0603FR-071K13L" 0603 22.748,25.235 r90 top value=1.13k (schematic designator R3)
R3_5 "RC0603FR-071K13L" 0603 22.647,18.649 r90 top value=1.13k (schematic designator R3)
R3_6 "RC0603FR-071K13L" 0603 22.647,13.671 r90 top value=1.13k (schematic designator R3)
R3_7 "RC0603FR-071K13L" 0603 22.647,8.671 r90 top value=1.13k (schematic designator R3)
R3_8 "RC0603FR-071K13L" 0603 22.647,3.671 r90 top value=1.13k (schematic designator R3)
R4_1 "CRCW0603200RJNEA" 0603 38.467,40.76 r180 top value=200 (schematic designator R4)
R4_2 "CRCW0603200RJNEA" 0603 38.467,35.79 r180 top value=200 (schematic designator R4)
R4_3 "CRCW0603200RJNEA" 0603 38.467,30.807 r180 top value=200 (schematic designator R4)
R4_4 "CRCW0603200RJNEA" 0603 38.467,25.821 r180 top value=200 (schematic designator R4)
R4_5 "CRCW0603200RJNEA" 0603 38.384,19.245 r180 top value=200 (schematic designator R4)
R4_6 "CRCW0603200RJNEA" 0603 38.404,14.25 r180 top value=200 (schematic designator R4)
R4_7 "CRCW0603200RJNEA" 0603 38.366,9.27 r180 top value=200 (schematic designator R4)
R4_8 "CRCW0603200RJNEA" 0603 38.388,4.276 r180 top value=200 (schematic designator R4)
R5_1 "RC0603FR-0766R5L" 0603 24.35,40.171 r270 top value=66.5 (schematic designator R5)
R5_2 "RC0603FR-0766R5L" 0603 24.35,35.192 r270 top value=66.5 (schematic designator R5)
R5_3 "RC0603FR-0766R5L" 0603 24.35,30.214 r270 top value=66.5 (schematic designator R5)
R5_4 "RC0603FR-0766R5L" 0603 24.35,25.235 r270 top value=66.5 (schematic designator R5)
R5_5 "RC0603FR-0766R5L" 0603 24.25,18.649 r270 top value=66.5 (schematic designator R5)
R5_6 "RC0603FR-0766R5L" 0603 24.25,13.671 r270 top value=66.5 (schematic designator R5)
R5_7 "RC0603FR-0766R5L" 0603 24.25,8.671 r270 top value=66.5 (schematic designator R5)
R5_8 "RC0603FR-0766R5L" 0603 24.25,3.671 r270 top value=66.5 (schematic designator R5)
R6_1 "RC0603FR-07806RL" 0603 44.431,39.587 r90 top value=806 (schematic designator R6)
R6_2 "RC0603FR-07806RL" 0603 44.431,34.608 r90 top value=806 (schematic designator R6)
R6_3 "RC0603FR-07806RL" 0603 44.431,29.63 r90 top value=806 (schematic designator R6)
R6_4 "RC0603FR-07806RL" 0603 44.431,24.651 r90 top value=806 (schematic designator R6)
R6_5 "RC0603FR-07806RL" 0603 44.33,18.066 r90 top value=806 (schematic designator R6)
R6_6 "RC0603FR-07806RL" 0603 44.33,13.087 r90 top value=806 (schematic designator R6)
R6_7 "RC0603FR-07806RL" 0603 44.331,8.087 r90 top value=806 (schematic designator R6)
R6_8 "RC0603FR-07806RL" 0603 44.33,3.087 r90 top value=806 (schematic designator R6)
R7_1 "RC0603FR-072K49L" 0603 29.251,40.171 r270 top value=2.49k (schematic designator R7)
R7_2 "RC0603FR-072K49L" 0603 29.251,35.192 r270 top value=2.49k (schematic designator R7)
R7_3 "RC0603FR-072K49L" 0603 29.251,30.214 r270 top value=2.49k (schematic designator R7)
R7_4 "RC0603FR-072K49L" 0603 29.251,25.235 r270 top value=2.49k (schematic designator R7)
R7_5 "RC0603FR-072K49L" 0603 29.15,18.649 r270 top value=2.49k (schematic designator R7)
R7_6 "RC0603FR-072K49L" 0603 29.15,13.671 r270 top value=2.49k (schematic designator R7)
R7_7 "RC0603FR-072K49L" 0603 29.15,8.671 r270 top value=2.49k (schematic designator R7)
R7_8 "RC0603FR-072K49L" 0603 29.15,3.671 r270 top value=2.49k (schematic designator R7)
R8 "RC0603JR-073K3L" 0603 71.324,13.93 r0 top value=3.3k
R9 "RC0603JR-0710KL" 0603 59.708,9.25 r180 top value=10k
R10 "RC0603JR-0710KL" 0603 48.791,3.05 r90 top value=10k
R11 "RC0603JR-0710KL" 0603 73.058,10.234 r180 top value=10k
R12 "RC0603JR-0710KL" 0603 69.805,10.225 r0 top value=10k
R13 "RC0603JR-0710KL" 0603 50.249,3.05 r90 top value=10k
R14 "RC0603JR-0747KL" 0603 73.064,11.975 r180 top value=47k
R15 "RC0603JR-0710KL" 0603 49.229,43.72 r180 top value=10k
R16 "RC0603JR-073K3L" 0603 56.908,41 r180 top value=3.3k
R17 "RC0603JR-0747KL" 0603 49.229,42.107 r0 top value=47k
R18 "CRCW06034R70JNEA" 0603 51.787,31.419 r0 top value=4.7
R19 "RC0603JR-0747KL" 0603 49.949,36.971 r90 top value=47k
R20 "RC0603FR-072K21L" 0603 57.458,11.661 r90 top value=2.21k
R21 "RC0603JR-0747KL" 0603 48.266,36.971 r90 top value=47k
R22 "RC0603JR-073K3L" 0603 52.61,35.067 r180 top value=3.3k
R23 "CRCW0603200RJNEA" 0603 47.347,29.5 r90 top value=200
R24 "RC0603JR-073K3L" 0603 73.708,27.625 r270 top value=3.3k
R25 "RC0603JR-071KL" 0603 46.607,36.971 r90 top value=1.0k
R26 "RC0603JR-0710KL" 0603 58.908,42.45 r270 top value=10k
R27 "RC0603JR-073K3L" 0603 58.914,45.527 r90 top value=3.3k
R28 "RC0603JR-0747KL" 0603 73.112,36.071 r0 top value=47k
R29 "RC0603JR-0747KL" 0603 54.208,48.302 r270 top value=47k
R30 "RC0603JR-0747KL" 0603 56.666,55.49 r270 top value=47k
R31 "RC0603FR-0782K5L" 0603 41.866,50.155 r180 top value=82.5k
R32 "RC0603FR-071RL" 0603 55.116,53.905 r90 top value=1.00
R33 "RC0603FR-0724K9L" 0603 41.07,47.907 r270 top value=24.9k
R34 "RC0603FR-0731K6L" 0603 48.039,47.164 r180 top value=31.6k
R35 "RC0603FR-0768K1L" 0603 23.616,53.5 r270 top value=68.1k
R36 "RC0603FR-0724K9L" 0603 25.116,55.25 r90 top value=24.9k
R37 "RC0603JR-0747KL" 0603 43.383,43.5 r180 top value=47k
R38 "RC0603JR-0747KL" 0603 49.239,45.316 r180 top value=47k
R39 "RC0603JR-0747KL" 0603 66.258,54.615 r90 top value=47k
R40 "RC0603FR-0753K6L" 0603 62.823,54.446 r270 top value=53.6k
R41 "RC0603FR-07249KL" 0603 44.217,49.376 r270 top value=249k
R42 "RC0603JR-0747KL" 0603 56.411,48.75 r0 top value=47k
R43 "RC0603FR-071K24L" 0603 45.708,47.4 r270 top value=1.24k
R44 "RC0603FR-072K15L" 0603 63.082,57.658 r90 top value=2.15k
R45 "RC0603FR-07196KL" 0603 56.666,51.157 r90 top value=196k
R46 "RC0603FR-0724K9L" 0603 59.627,48.75 r0 top value=24.9k
R47 "RC0603FR-0724K9L" 0603 45.708,44.25 r270 top value=24.9k
R48 "RC0603FR-0724K9L" 0603 65.458,58.477 r0 top value=24.9k
R49 "RC0603JR-0747KL" 0603 24.256,46.59 r90 top value=47k
R50 "RC0603JR-0747KL" 0603 38.708,45.58 r270 top value=47k
R51 "RC0603JR-0747KL" 0603 18.833,44.25 r0 top value=47k
R52 "RC0603FR-07562KL" 0603 22.747,46.59 r90 top value=562k
R53 "RC0603FR-0713KL" 0603 21.347,48.102 r90 top value=13.0k
R54 "RC0603FR-077K5L" 0603 17.208,50.948 r0 top value=7.50k
R55 "RC0603FR-0724K9L" 0603 20.458,50.948 r180 top value=24.9k
R56 "RC0603JR-0747KL" 0603 47.347,15.768 r270 top value=47k
R57 "RC0603JR-073K3L" 0603 55.211,10.7 r180 top value=3.3k
R58 "RC0603JR-073K3L" 0603 55.208,9.225 r180 top value=3.3k
R59 "RC0603JR-073K3L" 0603 55.208,12.107 r180 top value=3.3k
R60 "RC0603FR-07165KL" 0603 34.458,55.113 r90 top value=165k
R61 "RC1206FR-0714K7L" 1206 30.708,54.69 r180 top value=14.7k
R62 "RC0603FR-0724K9L" 0603 33.504,57.397 r180 top value=24.9k
R63 "RC0603JR-073K3L" 0603 46.533,7.25 r0 top value=3.3k
R64 "RC0603FR-07806RL" 0603 45.818,3.1 r270 top value=806
S1 "RS-032G05A3-SM RT" SW_RS-032G05A3-SM 56.458,6.625 r0 top
S2 "RS-032G05A3-SM RT" SW_RS-032G05A3-SM 56.458,2.805 r0 top
TP6 "TP_SM_1MM" TP_SM_1MM 73.708,17.25 r90 top
TP7 "TP_SM_1MM" TP_SM_1MM 48.942,17.514 r0 top
TP8 "TP_SM_1MM" TP_SM_1MM 59.083,35.25 r90 top
TP9 "TP_SM_1MM" TP_SM_1MM 48.466,31.481 r90 top
TP11 "5015" Testpoint_Keystone_Miniature 2.75,58.174 r180 top
TP12 "5015" Testpoint_Keystone_Miniature 7.75,58.174 r180 top
TP13 "5015" Testpoint_Keystone_Miniature 12.822,58.17 r180 top
TP14 "5015" Testpoint_Keystone_Miniature 17.891,58.174 r180 top
TP15 "TP_SM_1MM" TP_SM_1MM 26.916,51 r90 top
TP19 "TP_SM_1MM" TP_SM_1MM 21.131,43.5 r90 top
TP20 "TP_SM_1MM" TP_SM_1MM 26.135,44.25 r0 top
U1_1 "SN74LVC1G125DRLR" DRL0005A 39.675,38.95 r180 top (schematic designator U1)
U1_2 "SN74LVC1G125DRLR" DRL0005A 39.675,33.971 r180 top (schematic designator U1)
U1_3 "SN74LVC1G125DRLR" DRL0005A 39.675,28.993 r180 top (schematic designator U1)
U1_4 "SN74LVC1G125DRLR" DRL0005A 39.675,24.014 r180 top (schematic designator U1)
U1_5 "SN74LVC1G125DRLR" DRL0005A 39.575,17.428 r180 top (schematic designator U1)
U1_6 "SN74LVC1G125DRLR" DRL0005A 39.575,12.45 r180 top (schematic designator U1)
U1_7 "SN74LVC1G125DRLR" DRL0005A 39.575,7.45 r180 top (schematic designator U1)
U1_8 "SN74LVC1G125DRLR" DRL0005A 39.575,2.45 r180 top (schematic designator U1)
U2_1 "TLV9001IDCKR" DCK0005A_N 33.654,39.011 r0 top (schematic designator U2)
U2_2 "TLV9001IDCKR" DCK0005A_N 33.654,34.033 r0 top (schematic designator U2)
U2_3 "TLV9001IDCKR" DCK0005A_N 33.654,29.054 r0 top (schematic designator U2)
U2_4 "TLV9001IDCKR" DCK0005A_N 33.654,24.076 r0 top (schematic designator U2)
U2_5 "TLV9001IDCKR" DCK0005A_N 33.554,17.49 r0 top (schematic designator U2)
U2_6 "TLV9001IDCKR" DCK0005A_N 33.554,12.511 r0 top (schematic designator U2)
U2_7 "TLV9001IDCKR" DCK0005A_N 33.554,7.511 r0 top (schematic designator U2)
U2_8 "TLV9001IDCKR" DCK0005A_N 33.554,2.511 r0 top (schematic designator U2)
U3_1 "TVS0500DRVR" DRV0006A 20.681,38.975 r90 top (schematic designator U3)
U3_2 "TVS0500DRVR" DRV0006A 20.681,33.996 r90 top (schematic designator U3)
U3_3 "TVS0500DRVR" DRV0006A 20.681,29.018 r90 top (schematic designator U3)
U3_4 "TVS0500DRVR" DRV0006A 20.681,24.039 r90 top (schematic designator U3)
U3_5 "TVS0500DRVR" DRV0006A 20.581,17.453 r90 top (schematic designator U3)
U3_6 "TVS0500DRVR" DRV0006A 20.581,12.475 r90 top (schematic designator U3)
U3_7 "TVS0500DRVR" DRV0006A 20.581,7.475 r90 top (schematic designator U3)
U3_8 "TVS0500DRVR" DRV0006A 20.581,2.475 r90 top (schematic designator U3)
U4_1 "TVS0500DRVR" DRV0006A 20.681,41.5 r270 top (schematic designator U4)
U4_2 "TVS0500DRVR" DRV0006A 20.681,36.521 r270 top (schematic designator U4)
U4_3 "TVS0500DRVR" DRV0006A 20.681,31.543 r270 top (schematic designator U4)
U4_4 "TVS0500DRVR" DRV0006A 20.681,26.564 r270 top (schematic designator U4)
U4_5 "TVS0500DRVR" DRV0006A 20.581,19.978 r270 top (schematic designator U4)
U4_6 "TVS0500DRVR" DRV0006A 20.581,15 r270 top (schematic designator U4)
U4_7 "TVS0500DRVR" DRV0006A 20.581,10 r270 top (schematic designator U4)
U4_8 "TVS0500DRVR" DRV0006A 20.581,5 r270 top (schematic designator U4)
U5_1 "TL431LIAQDBZR" DBZ0003A_N 26.808,40.65 r90 top (schematic designator U5)
U5_2 "TL431LIAQDBZR" DBZ0003A_N 26.808,35.671 r90 top (schematic designator U5)
U5_3 "TL431LIAQDBZR" DBZ0003A_N 26.808,30.693 r90 top (schematic designator U5)
U5_4 "TL431LIAQDBZR" DBZ0003A_N 26.808,25.714 r90 top (schematic designator U5)
U5_5 "TL431LIAQDBZR" DBZ0003A_N 26.708,19.128 r90 top (schematic designator U5)
U5_6 "TL431LIAQDBZR" DBZ0003A_N 26.708,14.15 r90 top (schematic designator U5)
U5_7 "TL431LIAQDBZR" DBZ0003A_N 26.708,9.15 r90 top (schematic designator U5)
U5_8 "TL431LIAQDBZR" DBZ0003A_N 26.708,4.15 r90 top (schematic designator U5)
U6 "SN74LVC2G132DCUR" DCU0008A_N 52.925,45.05 r0 top
U7 "RM41L232BPZT" PZ0100A_M 60.458,22 r180 top
U8 "TPS3852H33DRBR" DRB0008A 52.6,40.55 r270 top
U9 "REF3030AIDBZT" DBZ0003A_N 58.608,32.668 r0 top
U10 "SN74LVC1G11DCKR" DCK0006A_N 52.6,37 r0 top
U11 "TPS22917DBVR" DBV0006A_N 56.493,35.79 r0 top
U12 "TL431LIBQDBZR" DBZ0003A_N 48.389,26.264 r180 top
U13 "ISO7741FQDWRQ1" DW0016B_HV 66.008,42.825 r180 top
U14 "LMR36006BRNXT" RNX0012B 38.866,51.231 r0 top
U15 "LM5166YDRCR" DRC0010J 51.616,48.155 r0 top
U16 "TPS622318DRYT" DRY0006A 60.366,56.606 r270 top
U17 "TPS3700DSER" DSE0006A 59.083,50.355 r0 top
U18 "TPS3700DSER" DSE0006A 44.183,46.655 r90 top
U19 "TPS3700DSER" DSE0006A 64.573,55.113 r270 top
U20 "TMP302CDRLR" DRL0006A 36.994,45.58 r90 top
U21 "TPS26624DRCR" DRC0010J 18.708,48.25 r180 top
U22 "SN74AHC594PW" PW0016A_N 49.939,11.43 r0 top
U23 "SN74LVC1G125DRLR" DRL0005A 49.579,5.647 r0 top
U24 "TL431LIAQDBZR" DBZ0003A_N 29.75,57.75 r0 top
Y1 "ABM3-16.000MHZ-D2Y-T" XTAL_ABM3 71.208,23 r90 top
ZZ1 "This Assembly Note is for PCB labels only" AssemblyNoteLabel 90.673,6.286 r90 top
ZZ2 "These assemblies are ESD sensitive, ESD precautions shall be observed." AssemblyNote 86.173,69.286 r90 top
ZZ3 "These assemblies must be clean and free from flux and all contaminants. Use of no clean flux is not acceptable." AssemblyNote 81.673,29.786 r90 top
ZZ4 "These assemblies must comply with workmanship standards IPC-A-610 Class 2, unless otherwise specified." AssemblyNote 77.173,38.286 r90 top

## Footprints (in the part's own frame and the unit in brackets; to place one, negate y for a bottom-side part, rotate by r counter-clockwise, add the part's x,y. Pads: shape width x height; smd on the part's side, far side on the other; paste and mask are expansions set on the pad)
0603 [mm] "0603 from SM-752 data"
  rect 1x0.95 smd: 1(-0.8,0) 2(0.8,0)
  silkscreen extent -1.52,-0.69 1.52,0.69, body extent -0.87,-0.47 0.87,0.47, height 1
0805_HV [mil] "0805 with 30mil clearance between pads"
  rect 50x63 smd: 1(-40,0) 2(40,0)
  silkscreen extent -74,-40 74,40, body extent -43,-29 43,29, height 57
1206 [mm] "1206 from SM-752 data"
  rect 1.3x1.85 smd: 1(-1.45,0) 2(1.45,0)
  silkscreen extent -2.4,-1.21 2.4,1.21, body extent -1.7,-0.9 1.7,0.9, height 1.35
1812_280 [mm] "1812"
  rect 1.6x3.4 smd: 1(-2,0) 2(2,0)
  silkscreen extent -0.8,-1.6 0.8,1.6, body extent -2.4,-1.7 2.4,1.7, height 2.8
2010 [mm] "Chip Capacitor, Body 5.08x2.54mm, IPC Medium Density"
  rect 1.6x2.7 smd: 1(-2.3,0) 2(2.3,0)
  silkscreen extent -3.42,-1.65 3.42,1.65, body extent -2.73,-1.45 2.73,1.45, height 1.66
2220_250 [mm] "2220"
  rect 1.6x5.3 smd: 1(-2.6,0) 2(2.6,0)
  silkscreen extent -3.69,-2.94 3.69,2.94, body extent -2.95,-2.62 2.95,2.62, height 2.5
AssemblyNote [mm] "Assembly Note"
AssemblyNoteLabel [mm] "Assembly Note for PCB Labels"
Bumpon_SJ5003Transparent [mil] "3M Hemispherical Bumpon transparent"
  round 1 on Mech4: 0(0,0)
  silkscreen extent -228,-228 228,228, body extent -219,-219 219,219, height 197
CE_Mark_5mm [mm] "Minimum text height for CE Mark"
  silkscreen extent -3.5,-2.5 3.5,2.5
DBV0006A_N [mm] "SOT23, 6-Leads, Body 2.9x1.6mm, Pitch 0.95mm, Lead Span 2.8mm, IPC Medium Density"
  rrect17% 1x0.6 smd: 1(-1.375,0.95) 2(-1.375,0) 3(-1.375,-0.95) 4(1.375,-0.95) 5(1.375,0) 6(1.375,0.95)
  silkscreen extent -1.68,-1.55 0.5,1.55, body extent -1.42,-1.46 1.42,1.46, height 1.12
DBZ0003A_N [mm] "SOT23, 3-Leads, Body 2.9x1.3mm, Pitch 0.95mm, Lead Span 2.4mm, IPC Medium Density"
  rrect17% 1x0.6 smd: 1(-1.2,0.95) 2(-1.2,-0.95) 3(1.2,0)
  silkscreen extent 0.2,-1.5 0.7,1.5, body extent -1.26,-1.46 1.26,1.46, height 0.98
DCK0005A_N [mm] "SOT353, 5-Leads, Body 2x1.3mm, Pitch 0.65mm, Lead Span 2.1mm, IPC Medium Density"
  rrect25% 0.85x0.4 smd: 1(-1.125,0.65) 2(-1.125,0) 3(-1.125,-0.65) 4(1.125,-0.65) 5(1.125,0.65)
  silkscreen extent -1.48,-1.02 0.55,1.1, body extent -1.14,-1 1.14,1, height 0.95
DCK0006A_N [mm] "SOT23, 6-Leads, Body 2x1.3mm, Pitch 0.65mm, Lead Span 2.1mm, IPC Medium Density"
  rrect25% 0.85x0.4 smd: 1(-1.125,0.65) 2(-1.125,0) 3(-1.125,-0.65) 4(1.125,-0.65) 5(1.125,0) 6(1.125,0.65)
  silkscreen extent -1.5,-1.09 0.51,1.09, body extent -1.14,-1 1.14,1, height 0.95
DCU0008A_N [mm] "TSSOP, 8-Leads, Body 2x2.3mm, Pitch 0.5mm, IPC Medium Density"
  oval 0.8x0.3 smd: 1(-1.6,0.75) 2(-1.6,0.25) 3(-1.6,-0.25) 4(-1.6,-0.75) 5(1.6,-0.75) 6(1.6,-0.25) 7(1.6,0.25) 8(1.6,0.75)
  silkscreen extent -1.05,-1.05 0.38,1.05, body extent -1.56,-1 1.56,1, height 0.9
DRB0008A [mm] "VSON-8"
  rrect32% 0.6x0.31 smd: 1(-1.4,0.975) 2(-1.4,0.325) 3(-1.4,-0.325) 4(-1.4,-0.975) 5(1.4,-0.975) 6(1.4,-0.325) 7(1.4,0.325) 8(1.4,0.975)
  rrect7% 1.5x1.75 smd paste-0.75: 9(0,0)
  Top Layer region: -0.7,-0.875 -0.49,-0.875 -0.471,-0.879 -0.455,-0.89 -0.444,-0.906 -0.44,-0.925 -0.44,-0.925 -0.44,-1.65 -0.436,-1.669 -0.425,-1.685 -0.409,-1.696 -0.39,-1.7 -0.39,-1.7 -0.26,-1.7 -0.241,-1.696 -0.225,-1.685 -0.214,-1.669 -0.21,-1.65 -0.21,-1.65 -0.21,-0.925 -0.206,-0.906 -0.195,-0.89 -0.179,-0.879 -0.16,-0.875 -0.16,-0.875 0.16,-0.875 0.179,-0.879 0.195,-0.89 0.206,-0.906 0.21,-0.925 0.21,-0.925 0.21,-1.65 0.21,-1.65 0.214,-1.669 0.225,-1.685 0.241,-1.696 0.26,-1.7 0.26,-1.7 0.39,-1.7 0.409,-1.696 0.425,-1.685 0.436,-1.669 0.44,-1.65 0.44,-1.65 0.44,-0.925 0.444,-0.906 0.455,-0.89 0.471,-0.879 0.49,-0.875 0.49,-0.875 0.7,-0.875 0.719,-0.871 0.735,-0.86 0.746,-0.844 0.75,-0.825 0.75,-0.825 0.75,0.825 0.746,0.844 0.735,0.86 0.719,0.871 0.7,0.875 0.7,0.875 0.49,0.875 0.471,0.879 0.455,0.89 0.444,0.906 0.44,0.925 0.44,0.925 0.44,1.65 0.436,1.669 0.425,1.685 0.409,1.696 0.39,1.7 0.39,1.7 0.26,1.7 0.241,1.696 0.225,1.685 0.214,1.669 0.21,1.65 0.21,1.65 0.21,1.65 0.21,0.925 0.206,0.906 0.195,0.89 0.179,0.879 0.16,0.875 0.16,0.875 -0.16,0.875 -0.179,0.879 -0.195,0.89 -0.206,0.906 -0.21,0.925 -0.21,0.925 -0.21,1.65 -0.214,1.669 -0.225,1.685 -0.241,1.696 -0.26,1.7 -0.26,1.7 -0.39,1.7 -0.409,1.696 -0.425,1.685 -0.436,1.669 -0.44,1.65 -0.44,1.65 -0.44,0.925 -0.444,0.906 -0.455,0.89 -0.471,0.879 -0.49,0.875 -0.49,0.875 -0.7,0.875 -0.719,0.871 -0.735,0.86 -0.746,0.844 -0.75,0.825 -0.75,0.825 -0.75,-0.825 -0.746,-0.844 -0.735,-0.86 -0.719,-0.871 -0.7,-0.875
  silkscreen extent -1.73,-1.73 1.73,1.73, body extent -1.5,-1.5 1.5,1.5, height 0.77
DRC0010J [mm] "VSON-10"
  rrect40% 0.6x0.25 smd: 1(-1.4,1) 2(-1.4,0.5) 3(-1.4,0) 4(-1.4,-0.5) 5(-1.4,-1) 6(1.4,-1) 7(1.4,-0.5) 8(1.4,0) 9(1.4,0.5) 10(1.4,1)
  rrect12% 1.65x2.4 smd paste-1 mask-2: 11(0,0)
  Top Layer region: -0.375,-1.65 -0.375,-1.2 -0.775,-1.2 -0.794,-1.196 -0.81,-1.185 -0.821,-1.169 -0.825,-1.15 -0.825,-1.15 -0.825,1.15 -0.821,1.169 -0.81,1.185 -0.794,1.196 -0.775,1.2 -0.775,1.2 -0.375,1.2 -0.375,1.65 -0.371,1.669 -0.36,1.685 -0.344,1.696 -0.325,1.7 -0.325,1.7 -0.325,1.7 -0.175,1.7 -0.175,1.7 -0.156,1.696 -0.14,1.685 -0.129,1.669 -0.125,1.65 -0.125,1.65 -0.125,1.2 0.125,1.2 0.125,1.65 0.129,1.669 0.14,1.685 0.156,1.696 0.175,1.7 0.175,1.7 0.175,1.7 0.325,1.7 0.325,1.7 0.344,1.696 0.36,1.685 0.371,1.669 0.375,1.65 0.375,1.65 0.375,1.2 0.775,1.2 0.794,1.196 0.81,1.185 0.821,1.169 0.825,1.15 0.825,1.15 0.825,-1.15 0.821,-1.169 0.81,-1.185 0.794,-1.196 0.775,-1.2 0.775,-1.2 0.375,-1.2 0.375,-1.65 0.371,-1.669 0.36,-1.685 0.344,-1.696 0.325,-1.7 0.325,-1.7 0.175,-1.7 0.156,-1.696 0.14,-1.685 0.129,-1.669 0.125,-1.65 0.125,-1.65 0.125,-1.2 -0.125,-1.2 -0.125,-1.65 -0.129,-1.669 -0.14,-1.685 -0.156,-1.696 -0.175,-1.7 -0.175,-1.7 -0.325,-1.7 -0.344,-1.696 -0.36,-1.685 -0.371,-1.669 -0.375,-1.65
  silkscreen extent -1.65,-1.65 1.65,1.65, body extent -1.5,-1.5 1.5,1.5, height 0.77
DRL0005A [mm] "SOTFL, 5-Flat Leads, Body 1.2x1.6x0.6mm, Pitch 0.5mm, TI recommended"
  rrect33% 0.67x0.3 smd: 1(-0.74,0.5) 2(-0.74,0) 3(-0.74,-0.5) 4(0.74,-0.5) 5(0.74,0.5)
  silkscreen extent -0.9,-0.95 0.5,0.95, body extent -0.85,-0.85 0.85,0.85, height 0.62
DRL0006A [mm] "SOTFL, 6-Flat Leads, Body 1.2x1.6x0.6mm, Pitch 0.5mm, TI recommended"
  rrect33% 0.67x0.3 smd: 1(-0.74,0.5) 2(-0.74,0) 3(-0.74,-0.5) 4(0.74,-0.5) 5(0.74,0) 6(0.74,0.5)
  silkscreen extent -0.9,-0.95 0.5,0.95, body extent -0.8,-0.8 0.8,0.8, height 0.61
DRV0006A [mm] "SON, 6-Leads, Body 2x2mm, Pitch 0.65mm, Thermal Pad 1.6x1mm, TI Recommended"
  rrect33% 0.45x0.3 smd: 1(-0.975,0.65) 2(-0.975,0) 3(-0.975,-0.65) 4(0.975,-0.65) 5(0.975,0) 6(0.975,0.65)
  rrect14% 1x0.7 on Top Paste: 7(0,0.45) 7(0,-0.45)
  rrect10% 1x1.6 smd paste-0.5: 7(0,0)
  silkscreen extent -1.05,-1.2 1.05,1.2, body extent -1.05,-1.05 1.05,1.05, height 0.81
DRY0006A [mm] "USON-6"
  rrect67% 0.45x0.3 smd paste-0.05 mask-0.05: 1(-0.275,0.5)
  rrect67% 0.4x0.3 smd paste-0.05 mask-0.05: 2(-0.3,0) 3(-0.3,-0.5) 4(0.3,-0.5) 5(0.3,0) 6(0.3,0.5)
  body extent -0.5,-0.72 0.5,0.73, height 0.58
DSE0006A [mm] "TI recommended land pattern"
  rect 0.66x0.25 smd: 1(-0.62,0.5)
  rect 0.7x0.25 smd: 2(-0.6,0) 3(-0.6,-0.5) 4(0.6,-0.5) 5(0.6,0) 6(0.6,0.5)
  Top Layer region: -0.3,0.625 -0.25,0.625 -0.15,0.525 -0.15,0.375 -0.3,0.375
  silkscreen extent -0.9,-0.92 0.9,0.92, body extent -0.77,-0.77 0.77,0.77, height 0.8
DW0016B_HV [mm] "SOIC-16, HV/isolation option"
  rrect17% 1.65x0.6 smd: 1(-4.875,4.445) 2(-4.875,3.175) 3(-4.875,1.905) 4(-4.875,0.635) 5(-4.875,-0.635) 6(-4.875,-1.905) 7(-4.875,-3.175) 8(-4.875,-4.445) 9(4.875,-4.445) 10(4.875,-3.175) 11(4.875,-1.905) 12(4.875,-0.635) 13(4.875,0.635) 14(4.875,1.905) 15(4.875,3.175) 16(4.875,4.445)
  body extent -5.17,-5.15 5.17,5.15, height 2.59
FCC_disclaimer [mm]
Fiducial10-20 [mm]
  round 1 smd mask+0.5: 1(0,0)
  Top Layer keep-out circle w1.178: c0,0 r0.5
Label_650x200 [mil] "Thermal Transfer Label"
  round 1 on Mech14: 0(0,0)
  silkscreen extent -325,-100 325,100, body extent -325,-100 325,100, height 1
Mini3-G3-B [mm] "SOT23, 3-Leads, Body 2.98x1.6mm, Pitch 0.95mm"
  rrect10% 1x1 smd: 1(-1.2,0.95) 2(-1.2,-0.95) 3(1.2,0)
  body extent -1.5,-1.55 1.5,1.55, height 1.4
Phoenix_1792863 [mm] "Terminal Block, 5mm, 2x1, R/A, TH"
  rrect50% 1.7x1.7 hole 1.2: 1(-2.5,0)
  round 1.7 hole 1.2: 2(2.5,0)
  silkscreen extent -5.6,-4.95 5,5.55, body extent -5,-4.95 5,5.55, height 13.6
Phoenix_1990067 [mm] "Terminal Block, 8x1, 2.5mm, TH"
  rect 1.5x1.5 hole 1: 1(-8.75,2.5)
  round 1.5 hole 1: 2(-6.25,-2.5) 3(-3.75,2.5) 4(-1.25,-2.5) 5(1.25,2.5) 6(3.75,-2.5) 7(6.25,2.5) 8(8.75,-2.5)
  silkscreen extent -11.5,-7.2 10,5.5, body extent -11.5,-7.2 10,4.8, height 13.11
PW0016A_N [mm] "TSOP, 16-Leads, Body 5x4.4mm, Pitch 0.65mm, IPC Medium Density"
  oval 1.4x0.45 smd: 1(-2.95,2.275) 2(-2.95,1.625) 3(-2.95,0.975) 4(-2.95,0.325) 5(-2.95,-0.325) 6(-2.95,-0.975) 7(-2.95,-1.625) 8(-2.95,-2.275) 9(2.95,-2.275) 10(2.95,-1.625) 11(2.95,-0.975) 12(2.95,-0.325) 13(2.95,0.325) 14(2.95,0.975) 15(2.95,1.625) 16(2.95,2.275)
  silkscreen extent -3.5,-2.55 1.85,2.75, body extent -3.21,-2.5 3.21,2.5, height 1
PZ0100A_M [mm] "TSQFP, 100-Leads, Body 16.2x16.2mm (max), Pitch 0.50mm, IPC Low Density"
  oval 1.65x0.3 smd: 1(-7.825,6) 2(-7.825,5.5) 3(-7.825,5) 4(-7.825,4.5) 5(-7.825,4) 6(-7.825,3.5) 7(-7.825,3) 8(-7.825,2.5) 9(-7.825,2) 10(-7.825,1.5) 11(-7.825,1) 12(-7.825,0.5) 13(-7.825,0) 14(-7.825,-0.5) 15(-7.825,-1) 16(-7.825,-1.5) 17(-7.825,-2) 18(-7.825,-2.5) 19(-7.825,-3) 20(-7.825,-3.5) 21(-7.825,-4) 22(-7.825,-4.5) 23(-7.825,-5) 24(-7.825,-5.5) 25(-7.825,-6) 51(7.825,-6) 52(7.825,-5.5) 53(7.825,-5) 54(7.825,-4.5) 55(7.825,-4) 56(7.825,-3.5) 57(7.825,-3) 58(7.825,-2.5) 59(7.825,-2) 60(7.825,-1.5) 61(7.825,-1) 62(7.825,-0.5) 63(7.825,0) 64(7.825,0.5) 65(7.825,1) 66(7.825,1.5) 67(7.825,2) 68(7.825,2.5) 69(7.825,3) 70(7.825,3.5) 71(7.825,4) 72(7.825,4.5) 73(7.825,5) 74(7.825,5.5) 75(7.825,6)
  oval 0.3x1.65 smd: 26(-6,-7.825) 27(-5.5,-7.825) 28(-5,-7.825) 29(-4.5,-7.825) 30(-4,-7.825) 31(-3.5,-7.825) 32(-3,-7.825) 33(-2.5,-7.825) 34(-2,-7.825) 35(-1.5,-7.825) 36(-1,-7.825) 37(-0.5,-7.825) 38(0,-7.825) 39(0.5,-7.825) 40(1,-7.825) 41(1.5,-7.825) 42(2,-7.825) 43(2.5,-7.825) 44(3,-7.825) 45(3.5,-7.825) 46(4,-7.825) 47(4.5,-7.825) 48(5,-7.825) 49(5.5,-7.825) 50(6,-7.825) 76(6,7.825) 77(5.5,7.825) 78(5,7.825) 79(4.5,7.825) 80(4,7.825) 81(3.5,7.825) 82(3,7.825) 83(2.5,7.825) 84(2,7.825) 85(1.5,7.825) 86(1,7.825) 87(0.5,7.825) 88(0,7.825) 89(-0.5,7.825) 90(-1,7.825) 91(-1.5,7.825) 92(-2,7.825) 93(-2.5,7.825) 94(-3,7.825) 95(-3.5,7.825) 96(-4,7.825) 97(-4.5,7.825) 98(-5,7.825) 99(-5.5,7.825) 100(-6,7.825)
  silkscreen extent -7.75,-6.2 6.2,6.82, body extent -8.01,-8.01 8.01,8.01, height 1.5
RNX0012B [mm] "VQFN-HR-12"
  rrect40% 0.6x0.25 smd: 1(-0.9,1.125) 2(-0.9,0.475) 3(-0.9,-0.175) 4(-0.9,-0.675) 8(0.9,-0.675) 9(0.9,-0.175) 10(0.9,0.475) 11(0.9,1.125)
  rrect40% 0.25x0.6 smd: 5(-0.5,-1.4) 6(0,-1.4) 7(0.5,-1.4)
  rrect40% 0.25x1.825 smd paste-0.175: 12(0,0.788)
  body extent -1,-1.5 1,1.5, height 1
Samtec_FTR-110-51-x-D-06 [mm] "Header, 1.27mm, 10x2, SMT"
  rect 2.87x0.711 smd: 1(-2.705,5.715) 2(2.705,5.715) 3(-2.705,4.445) 4(2.705,4.445) 5(-2.705,3.175) 6(2.705,3.175) 7(-2.705,1.905) 8(2.705,1.905) 9(-2.705,0.635) 10(2.705,0.635) 11(-2.705,-0.635) 12(2.705,-0.635) 13(-2.705,-1.905) 14(2.705,-1.905) 15(-2.705,-3.175) 16(2.705,-3.175) 17(-2.705,-4.445) 18(2.705,-4.445) 19(-2.705,-5.715) 20(2.705,-5.715)
  silkscreen extent -2.49,-6.35 2.49,6.7, body extent -3.76,-6.35 3.76,6.35, height 8.64
Samtec_HTSW-102-07-G-S [mm] "Samtec 100mil, 1x2, 230 mil above insulator"
  rrect6% 1.65x1.65 hole 1.016: 1(-1.27,0)
  round 1.65 hole 1.016: 2(1.27,0)
  silkscreen extent -3.3,-1.27 2.54,1.27, body extent -2.54,-1.27 2.54,1.27, height 8.38
SloBlo452 [mm] "Littelfuse 452/4 Fuses, recommended land pattern"
  rect 1.96x3.15 smd: 1(-2.455,0) 2(2.455,0)
  silkscreen extent -3.75,-1.88 3.75,1.9, body extent -3.05,-1.35 3.05,1.34, height 2.69
SMA_Bi [mm] "SMD, 2-Leads, Body 4.275x2.575mm"
  rect 1.4x1.64 smd: 1(-2.015,0) 2(2.015,0)
  silkscreen extent -2.3,-1.45 2.3,1.45, body extent -2.52,-1.45 2.52,1.45, height 2.65
SOT-523 [mm] "From Diodes Inc datasheet component parameters"
  rect 0.9x0.4 smd: 1(-0.8,0.5) 2(-0.8,-0.5) 3(0.8,0)
  silkscreen extent 0.02,-0.85 0.42,0.85, body extent -0.8,-0.8 0.8,0.8, height 0.79
SW_RS-032G05A3-SM [mm] "SMT, 2-Leads, Body 6x3.5mm, Pin Spacing 8mm"
  rect 2x2 smd: 1(-4,0) 2(4,0)
  silkscreen extent -3,-1.75 3,1.75, body extent -4,-1.75 4,1.75, height 4.3
Testpoint_Keystone_Miniature [mil] "Miniature SMT test point"
  rect 135x70 smd: 1(0,0)
  silkscreen extent -78,-46 78,45, body extent -52,-20 52,20, height 61
TP_SM_1MM [mm] "1mm Test Point, SMT"
  round 1 smd paste-0.5: 1(0,0)
WE-TPC_4828 [mm] "Wurth Elektronik recommended land pattern"
  rect 0.5x0.5 smd: 1(-2.35,0) 2(2.325,0)
  Top Layer region: 0.75,1.64 1.005,1.504 1.279,1.279 1.504,1.005 1.671,0.692 1.774,0.353 1.809,0 1.774,-0.353 1.671,-0.692 1.504,-1.005 1.279,-1.279 1.005,-1.504 0.75,-1.64 0.75,-2.65 2.75,-2.65 2.75,2.65 0.75,2.65
  Top Layer region: -0.75,1.64 -1.005,1.504 -1.279,1.279 -1.504,1.005 -1.671,0.692 -1.774,0.353 -1.809,0 -1.774,-0.353 -1.671,-0.692 -1.504,-1.005 -1.279,-1.279 -1.005,-1.504 -0.75,-1.64 -0.75,-2.65 -2.75,-2.65 -2.75,2.65 -0.75,2.65
  silkscreen extent -0.5,-2.6 0.5,2.63, body extent -2.5,-2.5 2.5,2.5, height 2
WEEE_Minimum [mm] "WEEElie bin"
  silkscreen extent -2.42,-4.38 2.52,2.65
WL-SMCW_GREEN [mm] "WURTH"
  rect 0.8x0.8 smd: 1(-0.8,0) 2(0.8,0)
  silkscreen extent -1.9,-0.8 1.2,0.8, body extent -0.85,-0.45 0.85,0.45, height 0.8
WL-SMCW_RED [mm] "WURTH"
  rect 0.8x0.8 smd: 1(-0.8,0) 2(0.8,0)
  silkscreen extent -1.9,-0.8 1.2,0.8, body extent -0.85,-0.45 0.85,0.45, height 0.8
WURTH_61300611121 [mm] "Header, 2.54mm, 6x1, TH"
  rrect50% 1.65x1.65 hole 1.15: 1(-6.35,0)
  round 1.65 hole 1.15: 2(-3.81,0) 3(-1.27,0) 4(1.27,0) 5(3.81,0) 6(6.35,0)
  body extent -7.62,-1.27 7.62,1.27, height 8.54
X1-DFN1006-2 [mm] "DIODES, INC"
  rect 0.4x0.7 smd: 1(-0.35,0) 2(0.35,0)
  silkscreen extent -0.8,-0.35 -0.8,0.35, body extent -0.54,-0.34 0.54,0.34, height 0.53
XTAL_ABM3 [mm] "Abracon recommended land pattern 12.28.10"
  rect 1.9x2.4 smd: 1(-2.05,0) 2(2.05,0)
  silkscreen extent -2.67,-1.78 2.67,1.78, body extent -2.6,-1.7 2.6,1.7, height 1.3
YJK0003A [mm] "SMD, 3-Leads, Body 1.49x0.73mm"
  rrect50% 0.2x0.39 on Top Paste: 1(-0.525,0) 2(0,0) 3(0.525,0)
  rrect80% 0.25x0.49 smd paste-0.15 mask-0.05: 1(-0.5,0) 2(0,0) 3(0.5,0)
  silkscreen extent -0.9,-0.5 0.9,0.5, body extent -0.75,-0.37 0.74,0.36, height 0.35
